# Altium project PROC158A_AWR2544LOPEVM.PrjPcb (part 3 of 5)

## Sheet PROC158A_Ethernet_PHY.SchDoc
size 431 x 279 mm; Date: Not shown in title block; ApprovedBy: Not shown in title block; CheckedBy: Not shown in title block; Author: Not shown in title block; CompanyName: Not shown in title block; Engineer: Not shown in title block; Organization: Not shown in title block; Address1: Not shown in title block; Address2: Not shown in title block; Address3: Not shown in title block; Address4: Not shown in title block; DocumentNumber: 12; Revision: Use project parameter SCH_Rev; SheetNumber: 12; SheetTotal: 24; PageSetup: Record=PageOptions¦CenterHorizontal=True¦CenterVertical=True¦PrintScale=1.00¦XCorrection=1.00¦YCorrection=1.00¦PrintKind=0¦BorderSize=5000000¦LeftOffset=0¦BottomOffset=0¦Orientation=2¦PaperLength=1000¦PaperWidth=1000¦Scale=100¦PaperSource=15¦PrintQuality=600¦MediaType=1¦DitherType=10¦PaperKind=Letter¦PrintScaleMode=1
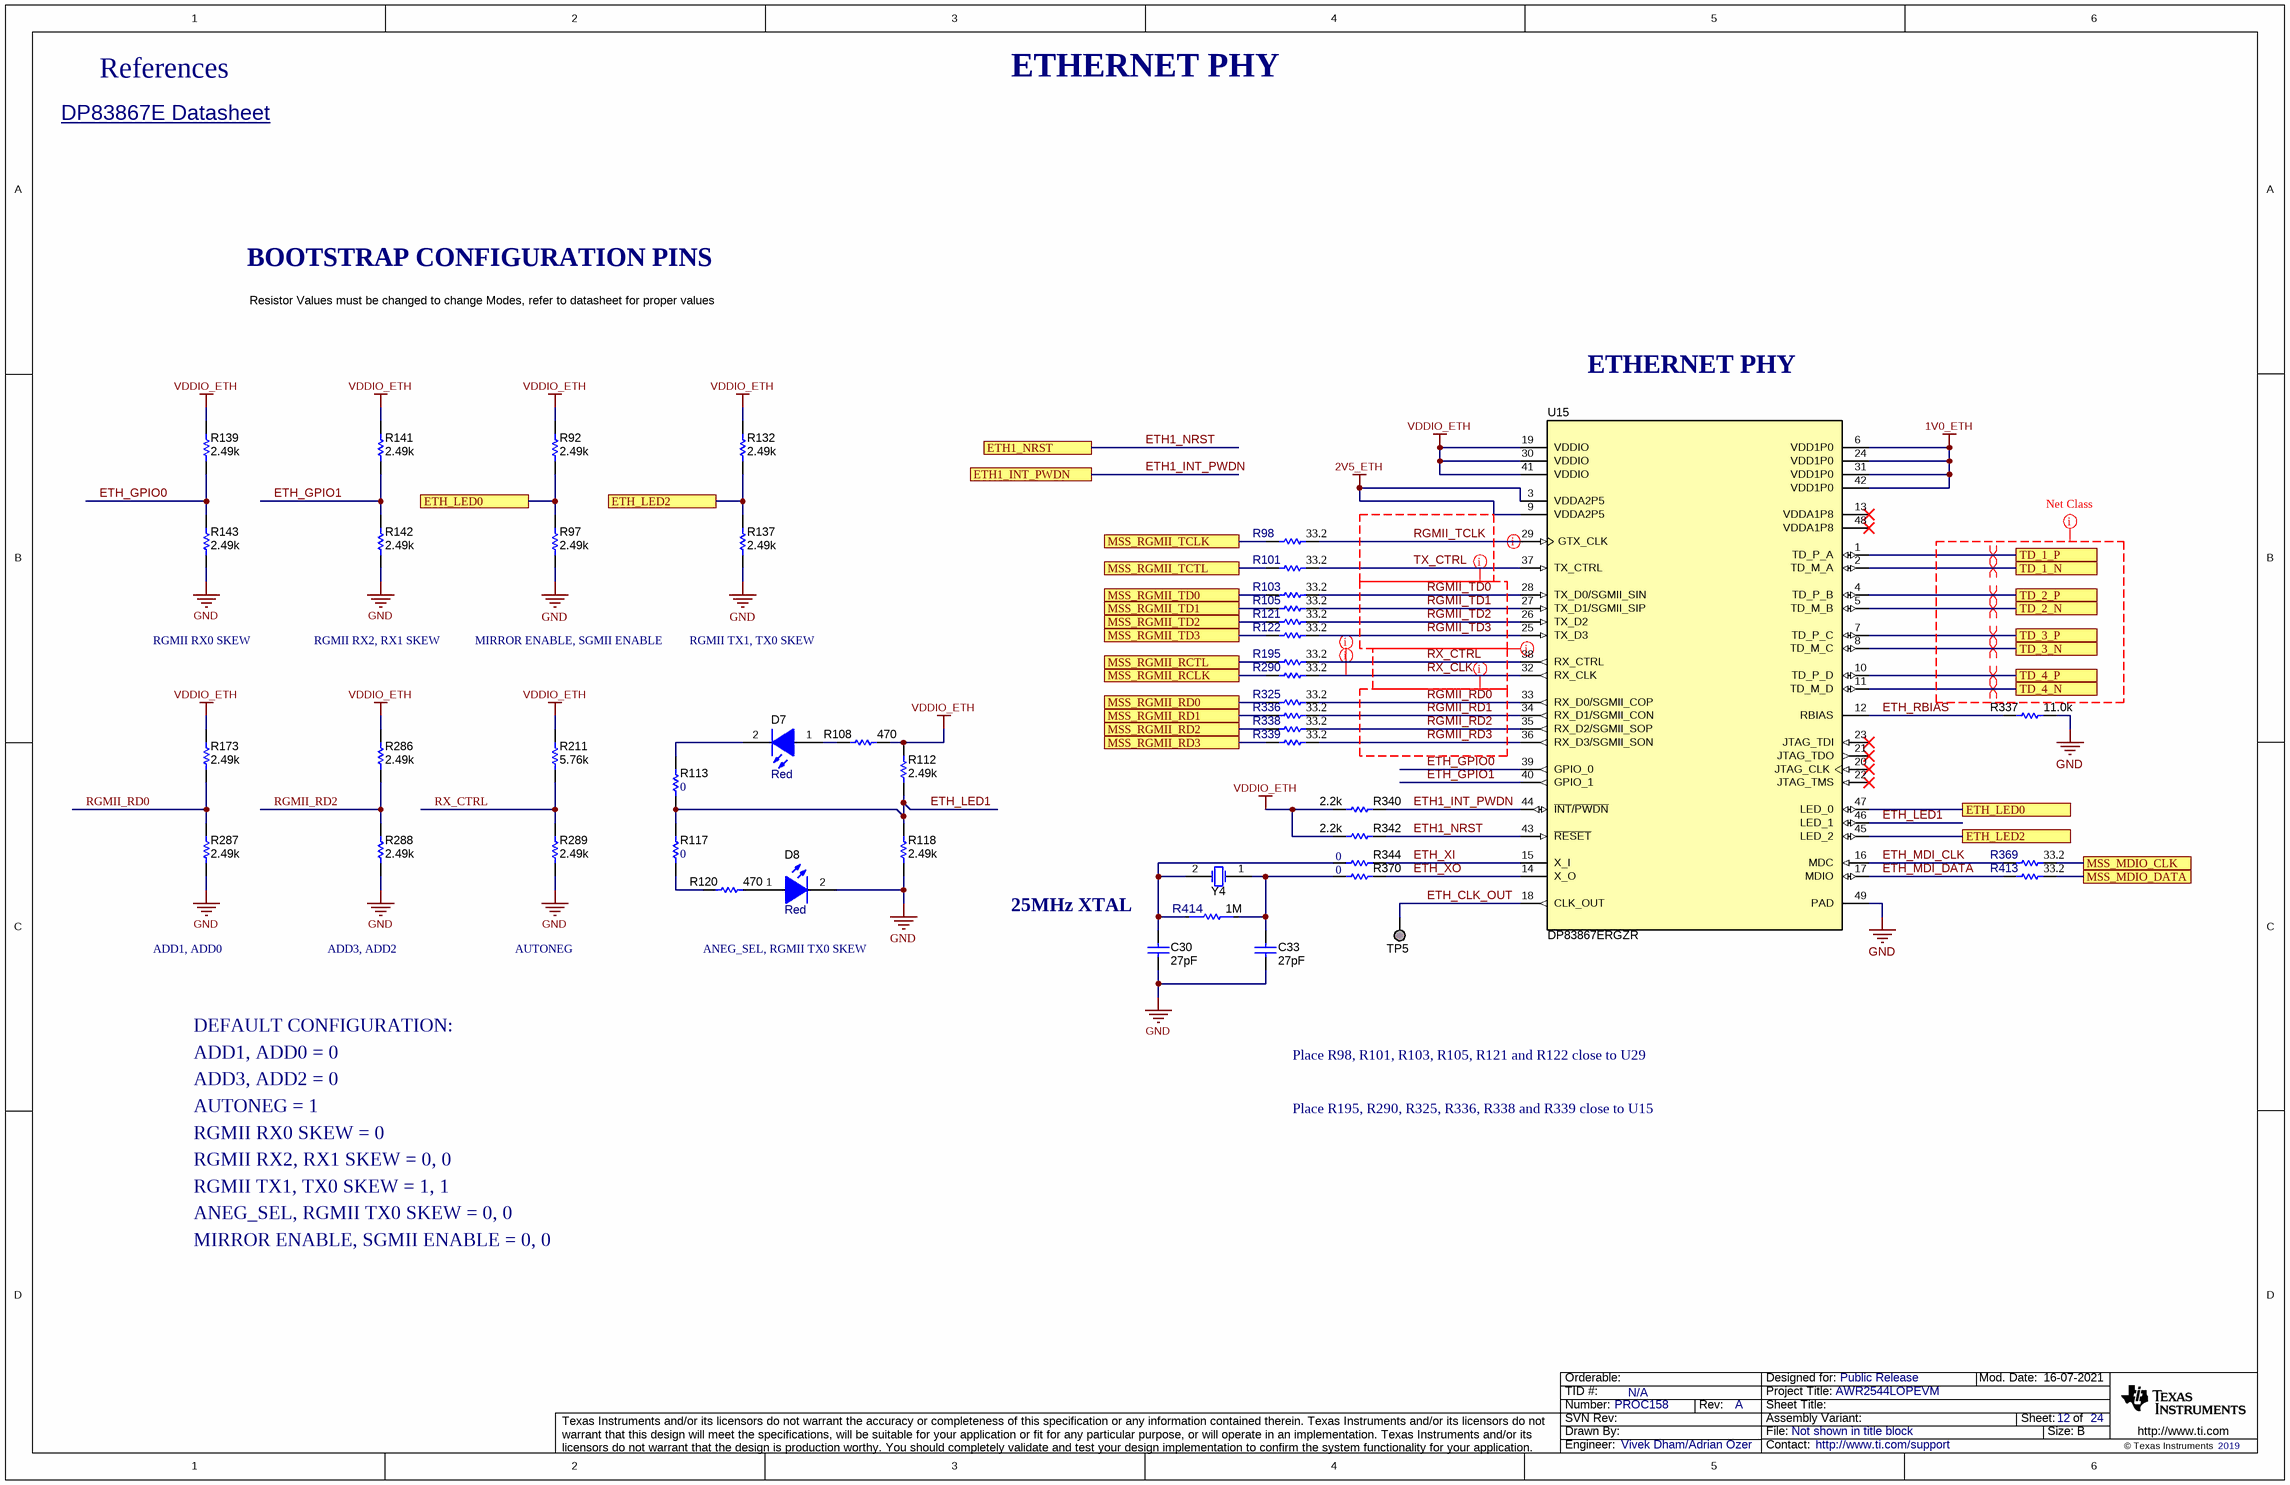
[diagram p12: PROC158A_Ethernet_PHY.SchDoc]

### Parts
C30  ValueDisplayed: 27pF  [0402L]  (hidden comment: GCM1555C1H270JA16D)
C33  ValueDisplayed: 27pF  [0402L]  (hidden comment: GCM1555C1H270JA16D)
D7  value Red  [LS L29K_Red]  (hidden comment: LS L29K-G1J2-1-Z)
D8  value Red  [LS L29K_Red]  (hidden comment: LS L29K-G1J2-1-Z)
R92  ValueDisplayed: 2.49k  [0402L]  (hidden comment: CRCW04022K49FKED)
R97  ValueDisplayed: 2.49k  [0402L]  (hidden comment: CRCW04022K49FKED)
R98  ValueDisplayed: 33.2  [0402L]  (hidden comment: CRCW040233R2FKED)
R101  ValueDisplayed: 33.2  [0402L]  (hidden comment: CRCW040233R2FKED)
R103  ValueDisplayed: 33.2  [0402L]  (hidden comment: CRCW040233R2FKED)
R105  ValueDisplayed: 33.2  [0402L]  (hidden comment: CRCW040233R2FKED)
R108  ValueDisplayed: 470  [0402L]  (hidden comment: ERJ-2RKF4700X)
R112  ValueDisplayed: 2.49k  [0402L]  (hidden comment: CRCW04022K49FKED)
R113  ValueDisplayed: 0  [0402L]  (hidden comment: ERJ-2GE0R00X)
R117  ValueDisplayed: 0  [0402L]  (hidden comment: ERJ-2GE0R00X)
R118  ValueDisplayed: 2.49k  [0402L]  (hidden comment: CRCW04022K49FKED)
R120  ValueDisplayed: 470  [0402L]  (hidden comment: ERJ-2RKF4700X)
R121  ValueDisplayed: 33.2  [0402L]  (hidden comment: CRCW040233R2FKED)
R122  ValueDisplayed: 33.2  [0402L]  (hidden comment: CRCW040233R2FKED)
R132  ValueDisplayed: 2.49k  [0402L]  (hidden comment: CRCW04022K49FKED)
R137  ValueDisplayed: 2.49k  [0402L]  (hidden comment: CRCW04022K49FKED)
R139  ValueDisplayed: 2.49k  [0402L]  (hidden comment: CRCW04022K49FKED)
R141  ValueDisplayed: 2.49k  [0402L]  (hidden comment: CRCW04022K49FKED)
R142  ValueDisplayed: 2.49k  [0402L]  (hidden comment: CRCW04022K49FKED)
R143  ValueDisplayed: 2.49k  [0402L]  (hidden comment: CRCW04022K49FKED)
R173  ValueDisplayed: 2.49k  [0402L]  (hidden comment: CRCW04022K49FKED)
R195  ValueDisplayed: 33.2  [0402L]  (hidden comment: CRCW040233R2FKED)
R211  ValueDisplayed: 5.76k  [0402L]  (hidden comment: CRCW04025K76FKED)
R286  ValueDisplayed: 2.49k  [0402L]  (hidden comment: CRCW04022K49FKED)
R287  ValueDisplayed: 2.49k  [0402L]  (hidden comment: CRCW04022K49FKED)
R288  ValueDisplayed: 2.49k  [0402L]  (hidden comment: CRCW04022K49FKED)
R289  ValueDisplayed: 2.49k  [0402L]  (hidden comment: CRCW04022K49FKED)
R290  ValueDisplayed: 33.2  [0402L]  (hidden comment: CRCW040233R2FKED)
R325  ValueDisplayed: 33.2  [0402L]  (hidden comment: CRCW040233R2FKED)
R336  ValueDisplayed: 33.2  [0402L]  (hidden comment: CRCW040233R2FKED)
R337  ValueDisplayed: 11.0k  [0402L]  (hidden comment: CRCW040211K0FKED)
R338  ValueDisplayed: 33.2  [0402L]  (hidden comment: CRCW040233R2FKED)
R339  ValueDisplayed: 33.2  [0402L]  (hidden comment: CRCW040233R2FKED)
R340  ValueDisplayed: 2.2k  [0402L]  (hidden comment: CRCW04022K20JNED)
R342  ValueDisplayed: 2.2k  [0402L]  (hidden comment: CRCW04022K20JNED)
R344  ValueDisplayed: 0  [0201L]  (hidden comment: CRCW02010000Z0ED)
R369  ValueDisplayed: 33.2  [0402L]  (hidden comment: CRCW040233R2FKED)
R370  ValueDisplayed: 0  [0201L]  (hidden comment: CRCW02010000Z0ED)
R413  ValueDisplayed: 33.2  [0402L]  (hidden comment: CRCW040233R2FKED)
R414  Res_ohm: 1M  [FP-CRCW06031M00FKEAC_0603-MFG]  (hidden comment: CRCW06031M00FKEAC)
TP5  TESTPOINT  [TP_25MIL-SMT]  (value not drawn)  (no BOM)
U15  DP83867ERGZR  [RGZ0048B]
Y4  ABM3-25.000MHZ-D2Y-T  [XTAL_ABM3]  (value not drawn)

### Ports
ETH1_INT_PWDN, ETH1_NRST, ETH_LED0, ETH_LED2, MSS_MDIO_CLK, MSS_MDIO_DATA, MSS_RGMII_RCLK, MSS_RGMII_RCTL, MSS_RGMII_RD0, MSS_RGMII_RD1, MSS_RGMII_RD2, MSS_RGMII_RD3, MSS_RGMII_TCLK, MSS_RGMII_TCTL, MSS_RGMII_TD0, MSS_RGMII_TD1, MSS_RGMII_TD2, MSS_RGMII_TD3, TD_1_N, TD_1_P, TD_2_N, TD_2_P, TD_3_N, TD_3_P, TD_4_N, TD_4_P

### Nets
1V0_ETH: U15.6(VDD1P0) U15.24(VDD1P0) U15.31(VDD1P0) U15.42(VDD1P0)
2V5_ETH: U15.3(VDDA2P5) U15.9(VDDA2P5)
GND: C30.2 C33.2 D8.2(K) R97.1 R118.1 R137.1 R142.1 R143.1 R287.1 R288.1 R289.1 R337.2 U15.49(PAD)
VDDIO_ETH: R92.2 R108.2 R112.2 R132.2 R139.2 R141.2 R173.2 R211.2 R286.2 R340.2 R342.2 U15.19(VDDIO) U15.30(VDDIO) U15.41(VDDIO)
ETH1_INT_PWDN: R340.1 U15.44(~{INT}/~{PWDN}) ; port ETH1_INT_PWDN
ETH1_NRST: R342.1 U15.43(~{RESET}) ; port ETH1_NRST
ETH_CLK_OUT: TP5.1 U15.18(CLK_OUT)
ETH_GPIO0: R139.1 R143.2 U15.39(GPIO_0)
ETH_GPIO1: R141.1 R142.2 U15.40(GPIO_1)
ETH_LED0: R92.1 R97.2 U15.47(LED_0) ; port ETH_LED0
ETH_LED1: R112.1 R113.1 R117.2 R118.2 U15.46(LED_1)
ETH_LED2: R132.1 R137.2 U15.45(LED_2) ; port ETH_LED2
ETH_MDI_CLK: R369.1 U15.16(MDC)
ETH_MDI_DATA: R413.1 U15.17(MDIO)
ETH_RBIAS: R337.1 U15.12(RBIAS)
ETH_XI: R344.2 U15.15(X_I)
ETH_XO: R370.2 U15.14(X_O)
MSS_MDIO_CLK: R369.2 ; port MSS_MDIO_CLK
MSS_MDIO_DATA: R413.2 ; port MSS_MDIO_DATA
MSS_RGMII_RCLK: R290.1 ; port MSS_RGMII_RCLK
MSS_RGMII_RCTL: R195.1 ; port MSS_RGMII_RCTL
MSS_RGMII_RD0: R325.1 ; port MSS_RGMII_RD0
MSS_RGMII_RD1: R336.1 ; port MSS_RGMII_RD1
MSS_RGMII_RD2: R338.1 ; port MSS_RGMII_RD2
MSS_RGMII_RD3: R339.1 ; port MSS_RGMII_RD3
MSS_RGMII_TCLK: R98.1 ; port MSS_RGMII_TCLK
MSS_RGMII_TCTL: R101.1 ; port MSS_RGMII_TCTL
MSS_RGMII_TD0: R103.1 ; port MSS_RGMII_TD0
MSS_RGMII_TD1: R105.1 ; port MSS_RGMII_TD1
MSS_RGMII_TD2: R121.1 ; port MSS_RGMII_TD2
MSS_RGMII_TD3: R122.1 ; port MSS_RGMII_TD3
RGMII_RD0: R173.1 R287.2 R325.2 U15.33(RX_D0/SGMII_COP)
RGMII_RD1: R336.2 U15.34(RX_D1/SGMII_CON)
RGMII_RD2: R286.1 R288.2 R338.2 U15.35(RX_D2/SGMII_SOP)
RGMII_RD3: R339.2 U15.36(RX_D3/SGMII_SON)
RGMII_TCLK: R98.2 U15.29(GTX_CLK)
RGMII_TD0: R103.2 U15.28(TX_D0/SGMII_SIN)
RGMII_TD1: R105.2 U15.27(TX_D1/SGMII_SIP)
RGMII_TD2: R121.2 U15.26(TX_D2)
RGMII_TD3: R122.2 U15.25(TX_D3)
RX_CLK: R290.2 U15.32(RX_CLK)
RX_CTRL: R195.2 R211.1 R289.2 U15.38(RX_CTRL)
TD_1_N: U15.2(TD_M_A) ; port TD_1_N
TD_1_P: U15.1(TD_P_A) ; port TD_1_P
TD_2_N: U15.5(TD_M_B) ; port TD_2_N
TD_2_P: U15.4(TD_P_B) ; port TD_2_P
TD_3_N: U15.8(TD_M_C) ; port TD_3_N
TD_3_P: U15.7(TD_P_C) ; port TD_3_P
TD_4_N: U15.11(TD_M_D) ; port TD_4_N
TD_4_P: U15.10(TD_P_D) ; port TD_4_P
TX_CTRL: R101.2 U15.37(TX_CTRL)
NetC30_1: C30.1 R344.1 R414.1 Y4.2(OSC2)
NetC33_1: C33.1 R370.1 R414.2 Y4.1(OSC1)
NetD7_1: D7.1(A) R108.1
NetD7_2: D7.2(K) R113.2
NetD8_1: D8.1(A) R120.2
NetR117_1: R117.1 R120.1

Not connected (* = marked no-connect by the designer): U15 13(VDDA1P8)* 20(JTAG_CLK)* 21(JTAG_TDO)* 22(JTAG_TMS)* 23(JTAG_TDI)* 48(VDDA1P8)*

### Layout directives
net class RGMII; net class RGMII_TX_RX: RGMII_RD0, RGMII_RD1, RGMII_RD2, RGMII_RD3, RGMII_TD0, RGMII_TD1, RGMII_TD2, RGMII_TD3
net class RGMII: (no net found under the mark), RX_CLK, RX_CTRL
differential pair: TD_1_N, TD_1_P, TD_2_N, TD_2_P, TD_3_N, TD_3_P, TD_4_N, TD_4_P
net class RGMII_TX_RX: RGMII_TCLK, RGMII_TD0, RGMII_TD1, RGMII_TD2, RGMII_TD3

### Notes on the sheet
- References
- ETHERNET PHY
- DP83867E Datasheet <http://www.ti.com/lit/ds/symlink/dp83867e.pdf>
- BOOTSTRAP CONFIGURATION PINS
- Resistor Values must be changed to change Modes, refer to datasheet for proper values
- RGMII RX0 SKEW
- RGMII RX2, RX1 SKEW
- MIRROR ENABLE, SGMII ENABLE
- RGMII TX1, TX0 SKEW
- ADD1, ADD0
- ADD3, ADD2
- AUTONEG
- ANEG_SEL, RGMII TX0 SKEW
- 25MHz XTAL
- DEFAULT CONFIGURATION:
- ADD1, ADD0 = 0
- ADD3, ADD2 = 0
- Place R98, R101, R103, R105, R121 and R122 close to U29
- AUTONEG = 1
- RGMII RX2, RX1 SKEW = 0, 0
- RGMII RX0 SKEW = 0
- Place R195, R290, R325, R336, R338 and R339 close to U15
- RGMII TX1, TX0 SKEW = 1, 1
- ANEG_SEL, RGMII TX0 SKEW = 0, 0
- MIRROR ENABLE, SGMII ENABLE = 0, 0

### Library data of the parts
C30 C33 = CMP-0860920-1: CAP, CERM, 27 pF, 50 V,+/- 5%, C0G/NP0, AEC-Q200 Grade 1, 0402; Manufacturer: MuRata; AEC Grade: 1; SizeZ_mm: 0.6; U/M: EA; Value: 27pF; SizeY_mm: 0.5; TaMax_C: 125°C; Polarized: N; AEC Qualified: Y; Cap_Case: 0402; AEC Category: Q200; Value2: 50V; SizeAreaWB_mm2: 3; TaMin_C: -55°C
D7 D8 = CMP-0002902-2: LED, Red, SMD; Manufacturer: OSRAM; Tjmax_C: 110°C; Vf_V: 1.8V; Vr_V: 12V; Io_A: 20mA; Angle: 160; Value1: W
R92 R97 R112 R118 R132 R137 R139 R141-R143 R173 R286-R289 = CMP-0026237-2: RES, 2.49 k, 1%, 0.063 W, AEC-Q200 Grade 0, 0402; Manufacturer: Vishay-Dale; Power_W: 63mW; TempCo: 100 ppm/C; Value_Code: 2k49; Value: 2.49k; EIA_Code: E96; SizeX_mm: 1; SizeY_mm: 0.5; SizeZ_mm: 0.6; Value2: 0.063W; AEC Qualified: Y; VDC_V: 50V; AEC Category: Q200; AEC Grade: 0
R98 R101 R103 R105 R121 R122 R195 R290 R325 R336 R338 R339 R369 R413 = CMP-0026299-2: RES, 33.2, 1%, 0.063 W, AEC-Q200 Grade 0, 0402; Manufacturer: Vishay-Dale; Power_W: 63mW; TempCo: 100 ppm/C; Value_Code: 33R2; Value: 33.2; EIA_Code: E96; SizeX_mm: 1; SizeY_mm: 0.5; SizeZ_mm: 0.6; Value2: 0.063W; AEC Qualified: Y; VDC_V: 50V; AEC Category: Q200; AEC Grade: 0
R108 R120 = CMP-0026699-1: RES, 470, 1%, 0.1 W, AEC-Q200 Grade 0, 0402; Manufacturer: Panasonic; Power_W: 100mW; TempCo: 100 ppm/C; Value_Code: 470R; U/M: EA; Value: 470; SizeX_mm: 1; SizeY_mm: 0.5; SizeZ_mm: 0.6; Value2: 0.1W; AEC Qualified: Y; VDC_V: 50V; AEC Grade: 0; AEC Category: Q200
R113 R117 = CMP-0026992-3: RES, 0, 5%, 0.1 W, AEC-Q200 Grade 0, 0402; Manufacturer: Panasonic; Power_W: 100mW; TempCo: 600 ppm/C; Value_Code: 0000; Value: 0; EIA_Code: E24; SizeX_mm: 1; SizeY_mm: 0.5; SizeZ_mm: 0.6; Value2: 0.1W; CompType: Resistor; AEC Qualified: Y; VDC_V: 50V; AEC Category: Q200; SizeAreaWB_mm2: 3; INSTALLATION: DNP
R211 = CMP-0026468-2: RES, 5.76 k, 1%, 0.063 W, AEC-Q200 Grade 0, 0402; Manufacturer: Vishay-Dale; Power_W: 63mW; TempCo: 100 ppm/C; Value_Code: 5k76; Value: 5.76k; EIA_Code: E96; SizeX_mm: 1; SizeY_mm: 0.5; SizeZ_mm: 0.6; Value2: 0.063W; AEC Qualified: Y; VDC_V: 50V; AEC Category: Q200; AEC Grade: 0
R337 = CMP-0025975-3: RES, 11.0 k, 1%, 0.063 W, AEC-Q200 Grade 0, 0402; Manufacturer: Vishay-Dale; Power_W: 63mW; TempCo: 100 ppm/C; Value_Code: 11k0; Value: 11.0k; EIA_Code: E96; Res_ohm: 11k; SizeX_mm: 1; SizeY_mm: 0.5; SizeZ_mm: 0.6; Value2: 0.063W; AEC Qualified: Y; VDC_V: 50V; AEC Category: Q200; AEC Grade: 0
R340 R342 = CMP-0026890-5: RES, 2.2 k, 5%, 0.063 W, AEC-Q200 Grade 0, 0402; Manufacturer: Vishay-Dale; Power_W: 63mW; TempCo: 200 ppm/C; Value_Code: 2k20; Value: 2.2k; EIA_Code: E24; SizeX_mm: 1; SizeY_mm: 0.5; SizeZ_mm: 0.6; Value2: 0.063W; AEC Qualified: Y; VDC_V: 50V; AEC Category: Q200; AEC Grade: 0
R344 R370 = CMP-0027008-4: RES, 0, 5%, 0.05 W, 0201; Manufacturer: Vishay-Dale; Power_W: 50mW; TempCo: ppm/C; Value_Code: 0000; Value: 0; EIA_Code: E24; SizeX_mm: 0.6; SizeY_mm: 0.3; SizeZ_mm: 0.26; Value2: 0.05W; SizeArea_mm2: 0.18; AEC Qualified: N; AEC Category: Q200
R414 = CMP-0089574-2: Res Thick Film 0603 1M Ohm 1% 1/10W ±100ppm/°C Molded SMD Paper T/R; Manufacturer: Vishay; AEC Qualified: No; Power_W: 100mW; AEC Grade: NA; SizeZ_mm: 0.55mm; VDC_V: 75V
TP5 = CMP-0078143-3: TEST POINT.  No entry in BOM.
U15 = CMP-0076013-2: Extended Temperature Gigabit Ethernet PHY with SGMII, RGZ0048B (VQFN-48); Manufacturer: Texas Instruments; Alternate PartNumber: DP83867ERGZT; SizeX_mm: 7; CompType: IC; SizeZ_mm: 1; SizeArea_mm2: 49; SizeAreaWB_mm2: 81; U/M: EA
Y4 = CMP-0004620-3: Crystal, 25 MHz, 18 pF, SMD; Manufacturer: Abracon Corporation; TaMin_C: -40°C; Frequency Stability: +/-30ppm; Frequency_Fixed: 25MHz; TaMax_C: 85°C

## Sheet PROC158A_Ethernet_Magnetics.SchDoc
size 431 x 279 mm; Date: Not shown in title block; ApprovedBy: Not shown in title block; CheckedBy: Not shown in title block; Author: Not shown in title block; CompanyName: Not shown in title block; Engineer: Not shown in title block; Organization: Not shown in title block; Address1: Not shown in title block; Address2: Not shown in title block; Address3: Not shown in title block; Address4: Not shown in title block; DocumentNumber: 13; Revision: Use project parameter SCH_Rev; SheetNumber: 13; SheetTotal: 24; PageSetup: Record=PageOptions¦CenterHorizontal=True¦CenterVertical=True¦PrintScale=1.00¦XCorrection=1.00¦YCorrection=1.00¦PrintKind=0¦BorderSize=5000000¦LeftOffset=0¦BottomOffset=0¦Orientation=2¦PaperLength=1000¦PaperWidth=1000¦Scale=100¦PaperSource=15¦PrintQuality=600¦MediaType=1¦DitherType=10¦PaperKind=Letter¦PrintScaleMode=1
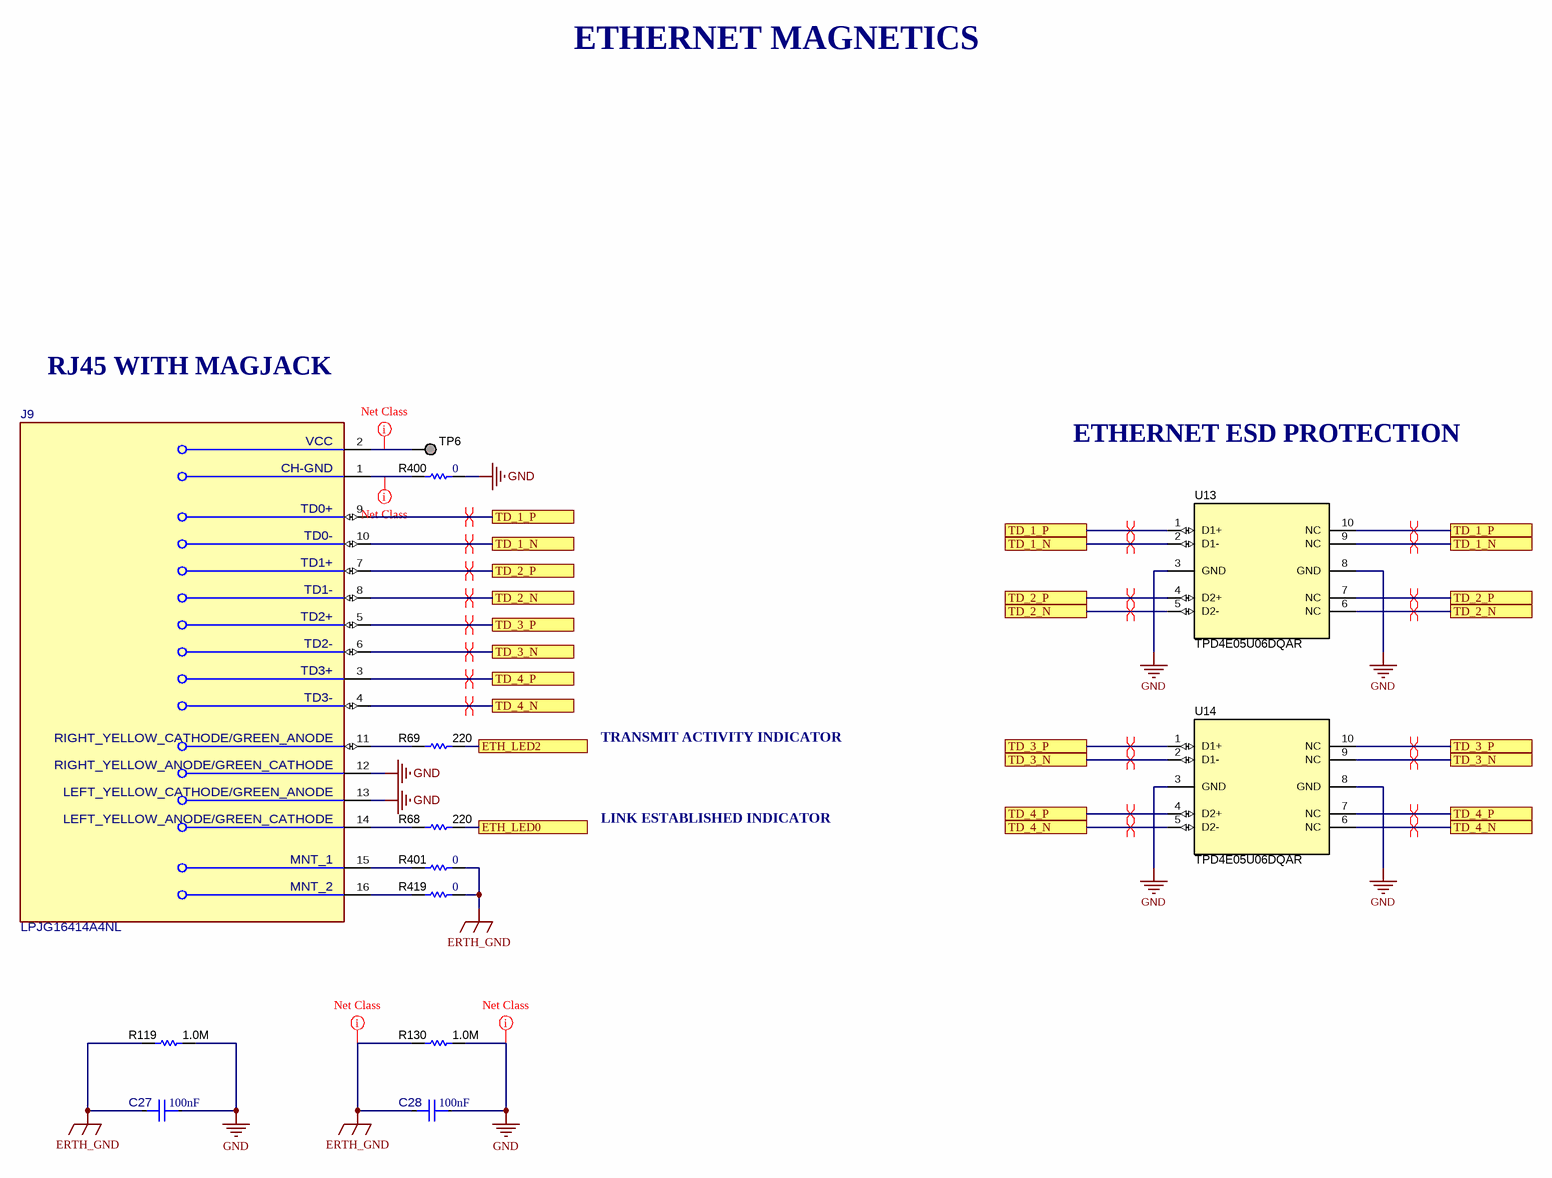
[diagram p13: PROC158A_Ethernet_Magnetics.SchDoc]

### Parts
C27  Cap_F: 100nF  [FP-C0603C104K4RACAUTO_0603-MFG]  (hidden comment: C0603C104K4RACAUTO)
C28  Cap_F: 100nF  [FP-C0603C104K4RACAUTO_0603-MFG]  (hidden comment: C0603C104K4RACAUTO)
J9  LPJG16414A4NL  [FP-LPJG16414A4NL_CONN_RJ45-MFG]
R68  ValueDisplayed: 220  [0402L]  (hidden comment: CRCW0402220RJNED)
R69  ValueDisplayed: 220  [0402L]  (hidden comment: CRCW0402220RJNED)
R119  ValueDisplayed: 1.0M  [1206L]  (hidden comment: CRCW12061M00JNEA)
R130  ValueDisplayed: 1.0M  [1206L]  (hidden comment: CRCW12061M00JNEA)
R400  ValueDisplayed: 0  [0402L]  (hidden comment: ERJ-2GE0R00X)
R401  ValueDisplayed: 0  [0402L]  (hidden comment: ERJ-2GE0R00X)
R419  ValueDisplayed: 0  [0402L]  (hidden comment: ERJ-2GE0R00X)
TP6  TESTPOINT  [TP_25MIL-SMT]  (value not drawn)  (no BOM)
U13  TPD4E05U06DQAR  [DQA0010A]
U14  TPD4E05U06DQAR  [DQA0010A]

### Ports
ETH_LED0, ETH_LED2, TD_1_N, TD_1_P, TD_2_N, TD_2_P, TD_3_N, TD_3_P, TD_4_N, TD_4_P

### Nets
ERTH_GND: C27.2 C28.2 R119.1 R130.1 R401.2 R419.2
GND: C27.1 C28.1 J9.12(RIGHT_YELLOW_ANODE/GREEN_CATHODE) J9.13(LEFT_YELLOW_CATHODE/GREEN_ANODE) R119.2 R130.2 R400.2 U13.3(GND) U13.8(GND) U14.3(GND) U14.8(GND)
ETH_LED0: R68.1 ; port ETH_LED0
ETH_LED2: R69.2 ; port ETH_LED2
TD_1_N: J9.10(TD0-) U13.2(D1-) U13.9(NC) ; port TD_1_N
TD_1_P: J9.9(TD0+) U13.1(D1+) U13.10(NC) ; port TD_1_P
TD_2_N: J9.8(TD1-) U13.5(D2-) U13.6(NC) ; port TD_2_N
TD_2_P: J9.7(TD1+) U13.4(D2+) U13.7(NC) ; port TD_2_P
TD_3_N: J9.6(TD2-) U14.2(D1-) U14.9(NC) ; port TD_3_N
TD_3_P: J9.5(TD2+) U14.1(D1+) U14.10(NC) ; port TD_3_P
TD_4_N: J9.4(TD3-) U14.5(D2-) U14.6(NC) ; port TD_4_N
TD_4_P: J9.3(TD3+) U14.4(D2+) U14.7(NC) ; port TD_4_P
NetJ9_1: J9.1(CH-GND) R400.1
NetJ9_2: J9.2(VCC) TP6.1
NetJ9_11: J9.11(RIGHT_YELLOW_CATHODE/GREEN_ANODE) R69.1
NetJ9_14: J9.14(LEFT_YELLOW_ANODE/GREEN_CATHODE) R68.2
NetJ9_15: J9.15(MNT_1) R401.1
NetJ9_16: J9.16(MNT_2) R419.1

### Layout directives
differential pair: TD_1_N, TD_1_P, TD_2_N, TD_2_P, TD_3_N, TD_3_P, TD_4_N, TD_4_P
net class PWR: ERTH_GND, GND, NetJ9_1, NetJ9_2

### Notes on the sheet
- ETHERNET MAGNETICS
- RJ45 WITH MAGJACK
- ETHERNET ESD PROTECTION
- TRANSMIT ACTIVITY INDICATOR
- LINK ESTABLISHED INDICATOR

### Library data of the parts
C27 C28 = CMP-0089508-1: C0603 0.10 μF X7R 30ppm/°C 10.00% 16 V; Manufacturer: KEMET; AEC Qualified: Yes; Tolerance_%: 0.1%; VDC_V: 16V; ValueDisplayed: 0.10 μF; AEC Grade: Grade 1; SizeZ_mm: 0.87mm
J9 = CMP-0088394-1: RJ45 Connector with 1000 Base-TX Inetgrated Magnetic; Manufacturer: LINK-PP; DUT-Pitch_mm: 1.27mm; Conn Orientation: Horizontal; ContactFinish: Gold; Conn Gender: Female; Is Female: yes; AEC Qualified: No; Shrouded: true
R68 R69 = CMP-0026878-3: RES, 220, 5%, 0.063 W, AEC-Q200 Grade 0, 0402; Manufacturer: Vishay-Dale; Power_W: 63mW; TempCo: 200 ppm/C; Value_Code: 220R; Value: 220; EIA_Code: E24; SizeX_mm: 1; SizeY_mm: 0.5; SizeZ_mm: 0.6; Value2: 0.063W; AEC Qualified: Y; VDC_V: 50V; AEC Category: Q200; AEC Grade: 0
R119 R130 = CMP-0018610-3: RES, 1.0 M, 5%, 0.25 W, AEC-Q200 Grade 0, 1206; Manufacturer: Vishay-Dale; Power_W: 250mW; TempCo: 200 ppm/C; Value_Code: 1M00; Value: 1.0Meg; EIA_Code: E24; Res_ohm: 1M; SizeX_mm: 3.2; SizeY_mm: 1.6; SizeZ_mm: 1.35; Value2: 0.25W; SizeArea_mm2: 5.12; AEC Qualified: Y; VDC_V: 200V; AEC Category: Q200; AEC Grade: 0
R400 R401 R419 = CMP-0026992-3: as R113 on sheet PROC158A_Ethernet_PHY
TP6 = CMP-0078143-3: TEST POINT.  No entry in BOM.
U13 U14 = CMP-0073613-3: 4-Channel Ultra-Low-Capacitance IEC ESD Protection Diode, DQA0010A (USON-10); Alternate Manufacturer: Texas Instruments; Green_Lifecycle: Active; SizeAreaWB_mm2: 7.0; Green_REACh: Passed; SizeZ_mm: 0.55; SizeX_mm: 1.0; SizeY_mm: 2.5; CompType: IC; AEC Category: Q200; AEC Qualified: N

## Sheet PROC158A_Auto_Ethernet_PHY.SchDoc
size 431 x 279 mm; Date: Not shown in title block; ApprovedBy: Not shown in title block; CheckedBy: Not shown in title block; Author: Not shown in title block; CompanyName: Not shown in title block; Engineer: Not shown in title block; Organization: Not shown in title block; Address1: Not shown in title block; Address2: Not shown in title block; Address3: Not shown in title block; Address4: Not shown in title block; DocumentNumber: 14; Revision: Use project parameter SCH_Rev; SheetNumber: 14; SheetTotal: 24; PageSetup: Record=PageOptions¦CenterHorizontal=True¦CenterVertical=True¦PrintScale=1.00¦XCorrection=1.00¦YCorrection=1.00¦PrintKind=0¦BorderSize=5000000¦LeftOffset=0¦BottomOffset=0¦Orientation=2¦PaperLength=1000¦PaperWidth=1000¦Scale=100¦PaperSource=15¦PrintQuality=600¦MediaType=1¦DitherType=10¦PaperKind=Letter¦PrintScaleMode=1
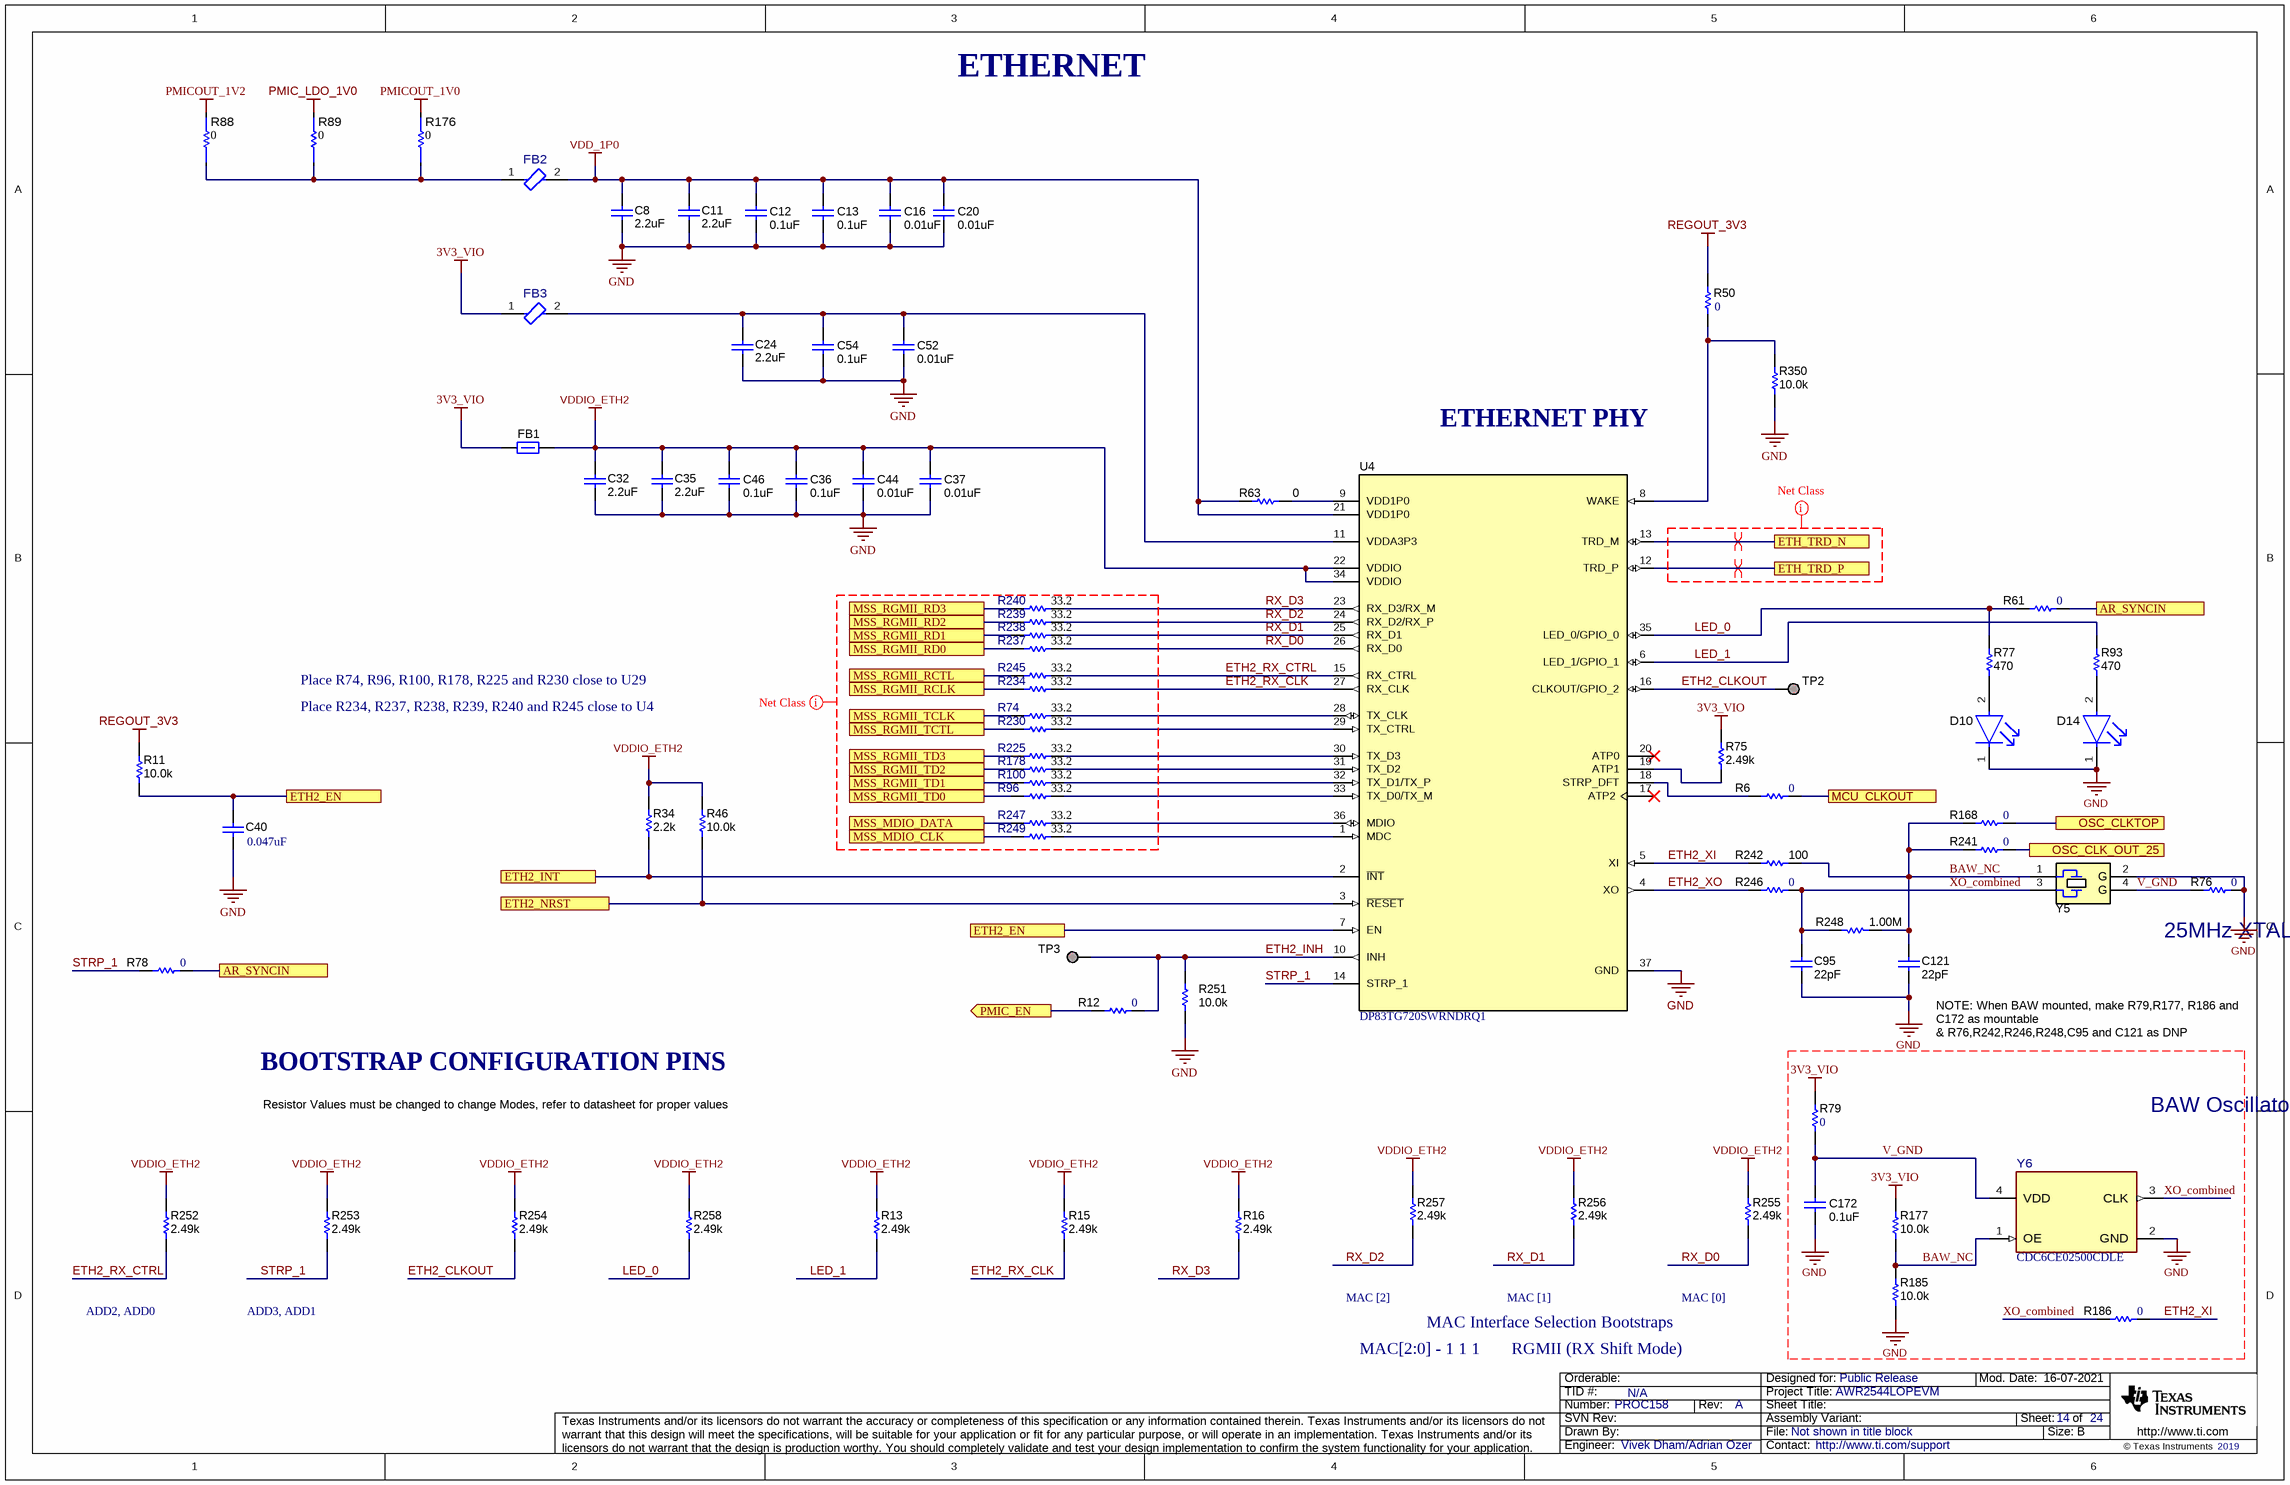
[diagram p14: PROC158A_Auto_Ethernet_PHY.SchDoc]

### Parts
C8  ValueDisplayed: 2.2uF  [0603L]  (hidden comment: GCM188R70J225KE22D)
C11  ValueDisplayed: 2.2uF  [0603L]  (hidden comment: GCM188R70J225KE22D)
C12  ValueDisplayed: 0.1uF  [0402L]  (hidden comment: GCM155R71C104KA55D)
C13  ValueDisplayed: 0.1uF  [0402L]  (hidden comment: GCM155R71C104KA55D)
C16  ValueDisplayed: 0.01uF  [0402L]  (hidden comment: CGA2B3X7R1H103K050BB)
C20  ValueDisplayed: 0.01uF  [0402L]  (hidden comment: CGA2B3X7R1H103K050BB)
C24  ValueDisplayed: 2.2uF  [0603L]  (hidden comment: GCM188R70J225KE22D)
C32  ValueDisplayed: 2.2uF  [0603L]  (hidden comment: GCM188R70J225KE22D)
C35  ValueDisplayed: 2.2uF  [0603L]  (hidden comment: GCM188R70J225KE22D)
C36  ValueDisplayed: 0.1uF  [0402L]  (hidden comment: GCM155R71C104KA55D)
C37  ValueDisplayed: 0.01uF  [0402L]  (hidden comment: CGA2B3X7R1H103K050BB)
C40  ValueDisplayed: 0.047uF  [0402]  (hidden comment: GRM155R71E473KA88D)
C44  ValueDisplayed: 0.01uF  [0402L]  (hidden comment: CGA2B3X7R1H103K050BB)
C46  ValueDisplayed: 0.1uF  [0402L]  (hidden comment: GCM155R71C104KA55D)
C52  ValueDisplayed: 0.01uF  [0402L]  (hidden comment: CGA2B3X7R1H103K050BB)
C54  ValueDisplayed: 0.1uF  [0402L]  (hidden comment: GCM155R71C104KA55D)
C95  ValueDisplayed: 22pF  [0603]  (hidden comment: CGA3E2C0G1H220J080AA)
C121  ValueDisplayed: 22pF  [0603]  (hidden comment: CGA3E2C0G1H220J080AA)
C172  ValueDisplayed: 0.1uF  [0402L]  (hidden comment: GCM155R71C104KA55D)
D10  SML-P12YTT86R  [FP-SML-P12YTT86R_0402-MFG]  (value not drawn)
D14  SML-P12DTT86R  [FP-SML-P12DTT86R_0402-MFG]  (value not drawn)
FB1  BLM18HE102SN1D  [0603]  (value not drawn)
FB2  BLM18KG601SH1  [FP-BLM18KG601SH1_0603 (1608 Metric)-MFG]  (value not drawn)
FB3  BLM18KG601SH1  [FP-BLM18KG601SH1_0603 (1608 Metric)-MFG]  (value not drawn)
R6  ValueDisplayed: 0  [0402L]  (hidden comment: ERJ-2GE0R00X)
R11  ValueDisplayed: 10.0k  [0402L]  (hidden comment: CRCW040210K0FKED)
R12  ValueDisplayed: 0  [0201L]  (hidden comment: CRCW02010000Z0ED)
R13  ValueDisplayed: 2.49k  [0402L]  (hidden comment: CRCW04022K49FKED)
R15  ValueDisplayed: 2.49k  [0402L]  (hidden comment: CRCW04022K49FKED)
R16  ValueDisplayed: 2.49k  [0402L]  (hidden comment: CRCW04022K49FKED)
R34  ValueDisplayed: 2.2k  [0402L]  (hidden comment: CRCW04022K20JNED)
R46  ValueDisplayed: 10.0k  [0402L]  (hidden comment: CRCW040210K0FKED)
R50  ValueDisplayed: 0  [0402L]  (hidden comment: ERJ-2GE0R00X)
R61  ValueDisplayed: 0  [0201L]  (hidden comment: CRCW02010000Z0ED)
R63  ValueDisplayed: 0  [0402]  (hidden comment: CRCW04020000Z0EDHP)
R74  ValueDisplayed: 33.2  [0402L]  (hidden comment: CRCW040233R2FKED)
R75  ValueDisplayed: 2.49k  [0402L]  (hidden comment: CRCW04022K49FKED)
R76  ValueDisplayed: 0  [0402L]  (hidden comment: ERJ-2GE0R00X)
R77  ValueDisplayed: 470  [0402L]  (hidden comment: ERJ-2RKF4700X)
R78  ValueDisplayed: 0  [0201L]  (hidden comment: CRCW02010000Z0ED)
R79  ValueDisplayed: 0  [0402L]  (hidden comment: ERJ-2GE0R00X)
R88  Res_ohm: 0  [FP-HCJ0603ZT0R00_0603-MFG]  (hidden comment: HCJ0603ZT0R00)
R89  Res_ohm: 0  [FP-HCJ0603ZT0R00_0603-MFG]  (hidden comment: HCJ0603ZT0R00)
R93  ValueDisplayed: 470  [0402L]  (hidden comment: ERJ-2RKF4700X)
R96  ValueDisplayed: 33.2  [0402L]  (hidden comment: CRCW040233R2FKED)
R100  ValueDisplayed: 33.2  [0402L]  (hidden comment: CRCW040233R2FKED)
R168  ValueDisplayed: 0  [0402L]  (hidden comment: ERJ-2GE0R00X)
R176  Res_ohm: 0  [FP-HCJ0603ZT0R00_0603-MFG]  (hidden comment: HCJ0603ZT0R00)
R177  ValueDisplayed: 10.0k  [0402L]  (hidden comment: CRCW040210K0FKED)
R178  ValueDisplayed: 33.2  [0402L]  (hidden comment: CRCW040233R2FKED)
R185  ValueDisplayed: 10.0k  [0402L]  (hidden comment: CRCW040210K0FKED)
R186  ValueDisplayed: 0  [0402L]  (hidden comment: ERJ-2GE0R00X)
R225  ValueDisplayed: 33.2  [0402L]  (hidden comment: CRCW040233R2FKED)
R230  ValueDisplayed: 33.2  [0402L]  (hidden comment: CRCW040233R2FKED)
R234  ValueDisplayed: 33.2  [0402L]  (hidden comment: CRCW040233R2FKED)
R237  ValueDisplayed: 33.2  [0402L]  (hidden comment: CRCW040233R2FKED)
R238  ValueDisplayed: 33.2  [0402L]  (hidden comment: CRCW040233R2FKED)
R239  ValueDisplayed: 33.2  [0402L]  (hidden comment: CRCW040233R2FKED)
R240  ValueDisplayed: 33.2  [0402L]  (hidden comment: CRCW040233R2FKED)
R241  ValueDisplayed: 0  [0402L]  (hidden comment: ERJ-2GE0R00X)
R242  ValueDisplayed: 100  [0402L]  (hidden comment: ERJ-2GEJ101X)
R245  ValueDisplayed: 33.2  [0402L]  (hidden comment: CRCW040233R2FKED)
R246  ValueDisplayed: 0  [0402L]  (hidden comment: ERJ-2GE0R00X)
R247  ValueDisplayed: 33.2  [0402L]  (hidden comment: CRCW040233R2FKED)
R248  ValueDisplayed: 1.00M  [0603L]  (hidden comment: CRCW06031M00FKEA)
R249  ValueDisplayed: 33.2  [0402L]  (hidden comment: CRCW040233R2FKED)
R251  ValueDisplayed: 10.0k  [0402L]  (hidden comment: CRCW040210K0FKED)
R252  ValueDisplayed: 2.49k  [0402L]  (hidden comment: CRCW04022K49FKED)
R253  ValueDisplayed: 2.49k  [0402L]  (hidden comment: CRCW04022K49FKED)
R254  ValueDisplayed: 2.49k  [0402L]  (hidden comment: CRCW04022K49FKED)
R255  ValueDisplayed: 2.49k  [0402L]  (hidden comment: CRCW04022K49FKED)
R256  ValueDisplayed: 2.49k  [0402L]  (hidden comment: CRCW04022K49FKED)
R257  ValueDisplayed: 2.49k  [0402L]  (hidden comment: CRCW04022K49FKED)
R258  ValueDisplayed: 2.49k  [0402L]  (hidden comment: CRCW04022K49FKED)
R350  ValueDisplayed: 10.0k  [0402L]  (hidden comment: CRCW040210K0FKED)
TP2  TESTPOINT  [TP_25MIL-SMT]  (value not drawn)  (no BOM)
TP3  TESTPOINT  [TP_25MIL-SMT]  (value not drawn)  (no BOM)
U4  DP83TG720SWRNDRQ1  [RND0036A]
Y5  ABM8AIG-25.000MHZ-12-2Z-T3  [Abracon_ABM8AIG]  (value not drawn)
Y6  CDC6CE02500CDLE  [DLE0004A-MFG]

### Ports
AR_SYNCIN, ETH2_EN, ETH2_INT, ETH2_NRST, ETH_TRD_N, ETH_TRD_P, MCU_CLKOUT, MSS_MDIO_CLK, MSS_MDIO_DATA, MSS_RGMII_RCLK, MSS_RGMII_RCTL, MSS_RGMII_RD0, MSS_RGMII_RD1, MSS_RGMII_RD2, MSS_RGMII_RD3, MSS_RGMII_TCLK, MSS_RGMII_TCTL, MSS_RGMII_TD0, MSS_RGMII_TD1, MSS_RGMII_TD2, MSS_RGMII_TD3, OSC_CLK_OUT_25, OSC_CLKTOP, PMIC_EN (out)

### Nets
3V3_VIO: FB1.1 FB3.1 R75.2 R79.1 R177.1
GND: C8.1 C11.1 C12.1 C13.1 C16.2 C20.2 C24.1 C32.1 C35.1 C36.1 C37.2 C40.2 C44.2 C46.1 C52.2 C54.1 C95.2 C121.2 C172.1 D10.1(CATHODE) D14.1(CATHODE) R76.1 R185.2 R251.2 R350.2 U4.37(GND) Y5.2(GND) Y6.2(GND)
PMIC_LDO_1V0: R89.2
PMICOUT_1V0: R176.2
PMICOUT_1V2: R88.2
REGOUT_3V3: R11.1 R50.2
VDD_1P0: C8.2 C11.2 C12.2 C13.2 C16.1 C20.1 FB2.2 R63.1 U4.21(VDD1P0)
VDDIO_ETH2: C32.2 C35.2 C36.2 C37.1 C44.1 C46.2 FB1.2 R13.2 R15.2 R16.2 R34.1 R46.1 R252.2 R253.2 R254.2 R255.2 R256.2 R257.2 R258.2 U4.22(VDDIO) U4.34(VDDIO)
AR_SYNCIN: R61.2 R78.2 ; port AR_SYNCIN
BAW_NC: C121.1 R168.2 R177.2 R185.1 R241.2 R242.2 R248.1 Y5.1 Y6.1(OE)
ETH2_CLKOUT: R254.1 TP2.1 U4.16(CLKOUT/GPIO_2)
ETH2_EN: C40.1 R11.2 U4.7(EN) ; port ETH2_EN
ETH2_INH: R12.2 R251.1 TP3.1 U4.10(INH)
ETH2_INT: R34.2 U4.2(~{INT}) ; port ETH2_INT
ETH2_NRST: R46.2 U4.3(~{RESET}) ; port ETH2_NRST
ETH2_RX_CLK: R15.1 R234.2 U4.27(RX_CLK)
ETH2_RX_CTRL: R245.2 R252.1 U4.15(RX_CTRL)
ETH2_XI: R186.1 R242.1 U4.5(XI)
ETH2_XO: R246.2 U4.4(XO)
ETH_TRD_N: U4.13(TRD_M) ; port ETH_TRD_N
ETH_TRD_P: U4.12(TRD_P) ; port ETH_TRD_P
LED_0: R61.1 R77.2 R258.1 U4.35(LED_0/GPIO_0)
LED_1: R13.1 R93.2 U4.6(LED_1/GPIO_1)
MCU_CLKOUT: R6.1 ; port MCU_CLKOUT
MSS_MDIO_CLK: R249.1 ; port MSS_MDIO_CLK
MSS_MDIO_DATA: R247.1 ; port MSS_MDIO_DATA
MSS_RGMII_RCLK: R234.1 ; port MSS_RGMII_RCLK
MSS_RGMII_RCTL: R245.1 ; port MSS_RGMII_RCTL
MSS_RGMII_RD0: R237.1 ; port MSS_RGMII_RD0
MSS_RGMII_RD1: R238.1 ; port MSS_RGMII_RD1
MSS_RGMII_RD2: R239.1 ; port MSS_RGMII_RD2
MSS_RGMII_RD3: R240.1 ; port MSS_RGMII_RD3
MSS_RGMII_TCLK: R74.1 ; port MSS_RGMII_TCLK
MSS_RGMII_TCTL: R230.1 ; port MSS_RGMII_TCTL
MSS_RGMII_TD0: R96.1 ; port MSS_RGMII_TD0
MSS_RGMII_TD1: R100.1 ; port MSS_RGMII_TD1
MSS_RGMII_TD2: R178.1 ; port MSS_RGMII_TD2
MSS_RGMII_TD3: R225.1 ; port MSS_RGMII_TD3
OSC_CLK_OUT_25: R241.1 ; port OSC_CLK_OUT_25
OSC_CLKTOP: R168.1 ; port OSC_CLKTOP
PMIC_EN: R12.1 ; port PMIC_EN
RX_D0: R237.2 R255.1 U4.26(RX_D0)
RX_D1: R238.2 R256.1 U4.25(RX_D1)
RX_D2: R239.2 R257.1 U4.24(RX_D2/RX_P)
RX_D3: R16.1 R240.2 U4.23(RX_D3/RX_M)
STRP_1: R78.1 R253.1 U4.14(STRP_1)
V_GND: C172.2 R76.2 R79.2 Y5.4(GND) Y6.4(VDD)
XO_combined: C95.1 R186.2 R246.1 R248.2 Y5.3 Y6.3(CLK)
NetC24_2: C24.2 C52.1 C54.2 FB3.2 U4.11(VDDA3P3)
NetD10_2: D10.2(ANODE) R77.1
NetD14_2: D14.2(ANODE) R93.1
NetFB2_1: FB2.1 R88.1 R89.1 R176.1
NetR6_2: R6.2 U4.18(STRP_DFT)
NetR50_1: R50.1 R350.1 U4.8(WAKE)
NetR63_2: R63.2 U4.9(VDD1P0)
NetR74_2: R74.2 U4.28(TX_CLK)
NetR75_1: R75.1 U4.19(ATP1)
NetR96_2: R96.2 U4.33(TX_D0/TX_M)
NetR100_2: R100.2 U4.32(TX_D1/TX_P)
NetR178_2: R178.2 U4.31(TX_D2)
NetR225_2: R225.2 U4.30(TX_D3)
NetR230_2: R230.2 U4.29(TX_CTRL)
NetR247_2: R247.2 U4.36(MDIO)
NetR249_2: R249.2 U4.1(MDC)

Not connected (* = marked no-connect by the designer): U4 17(ATP2)* 20(ATP0)*

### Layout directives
differential pair: ETH_TRD_N, ETH_TRD_P
net class RGMII: (no net found under the mark)

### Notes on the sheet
- ETHERNET
- ETHERNET PHY
- Place R74, R96, R100, R178, R225 and R230 close to U29
- Place R234, R237, R238, R239, R240 and R245 close to U4
- (near Y5) 25MHz XTAL
- (near C121) NOTE: When BAW mounted, make R79,R177, R186 and C172 as mountable
  & R76,R242,R246,R248,C95 and C121 as DNP
- BOOTSTRAP CONFIGURATION PINS
- Resistor Values must be changed to change Modes, refer to datasheet for proper values
- BAW Oscillator
- MAC [2]
- MAC [1]
- MAC [0]
- ADD2, ADD0
- ADD3, ADD1
- MAC[2:0] - 1 1 1       RGMII (RX Shift Mode)
- MAC Interface Selection Bootstraps

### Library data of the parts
C8 C11 C24 C32 C35 = CMP-0007134-5: CAP, CERM, 2.2 uF, 6.3 V, +/- 10%, X7R, AEC-Q200 Grade 1, 0603; Manufacturer: MuRata; TaMin_C: -55°C; Polarized: N; SizeAreaWB_mm2: 4.68; Value1: Unknown; U/M: EA; Value: 2.2uF; TaMax_C: 125°C; SizeZ_mm: 1; SizeX_mm: 1.6; SizeY_mm: 0.8; Cap_Case: 0603; Value2: 6.3V; SizeArea_mm2: 1.28; AEC Qualified: Y; Cap_F: 2.2µF; AEC Category: Q200
C12 C13 C36 C46 C54 C172 = CMP-0006351-2: CAP, CERM, 0.1 uF, 16 V, +/- 10%, X7R, 0402; Manufacturer: MuRata; TaMin_C: -55°C; Polarized: N; SizeAreaWB_mm2: 3; Value1: Unknown; U/M: EA; Value: 0.1uF; TaMax_C: 125°C; SizeZ_mm: 0.6; SizeX_mm: 1; SizeY_mm: 0.5; Cap_Case: 0402; Value2: 16V; CompType: Capacitor; Cap_F: 100nF; AEC Category: Q200
C16 C20 C37 C44 C52 = CMP-0006324-2: CAP, CERM, 0.01 uF, 50 V, +/- 10%, X7R, AEC-Q200 Grade 1, 0402; Manufacturer: TDK; TaMin_C: -55°C; ESR_ohm: 0.333065; Polarized: N; SizeAreaWB_mm2: 3; Value1: 0.333065 ohm; U/M: EA; Value: 0.01uF; TaMax_C: 125°C; SizeZ_mm: 0.6; SizeX_mm: 1; SizeY_mm: 0.5; Cap_Case: 0402; Value2: 50V; CompType: Capacitor; AEC Qualified: Y; Cap_F: 10nF; IRMS_A: 323.373mA; AEC Category: Q200
C40 = CMP-0006669-2: CAP, CERM, 0.047 uF, 25 V, +/- 10%, X7R, 0402; Manufacturer: MuRata; TaMin_C: -55°C; Polarized: N; SizeAreaWB_mm2: 3; Value1: Unknown; U/M: EA; TaMax_C: 125°C; SizeZ_mm: 0.6; SizeX_mm: 1; SizeY_mm: 0.5; Value2: 25V; Cap_F: 47nF; AEC Category: Q200
C95 C121 = CMP-0007071-4: CAP, CERM, 22 pF, 50 V, +/- 5%, C0G/NP0, AEC-Q200 Grade 1, 0603; Manufacturer: TDK; TaMin_C: -55°C; Polarized: N; SizeAreaWB_mm2: 4.68; Value1: Unknown; U/M: EA; Value: 22pF; TaMax_C: 125°C; SizeZ_mm: 1; SizeX_mm: 1.6; SizeY_mm: 0.8; Value2: 50V; SizeArea_mm2: 1.28; CompType: Capacitor; AEC Qualified: Y; AEC Category: Q200
D10 = CMP-0120222-1: Yellow 590nm LED Indication - Discrete 2.1V 0402 (1006 Metric); Manufacturer: Rohm Semiconductor; Power_TotalModule: 52mW; SizeZ_mm: 0.25mm; Tjmax_C: 110°C; Vr_V: 5V; AEC Qualified: No; Forward Current: 20mA; Led Orientation: Top View; Luminous Intensity: 100mcd
D14 = CMP-0120221-1: LED Uni-Color Orange 2-Pin Chip 0402(1006Metric) T/R; Manufacturer: Rohm Semiconductor; LambdaD: 605nm; Power_TotalModule: 52mW; SizeZ_mm: 0.25mm; Tjmax_C: 110°C; Vf_V: 2.1V; Vr_V: 5V; AEC Qualified: No; Forward Current: 20mA; Led Orientation: Top View; Luminous Intensity: 100mcd
FB1 = CMP-0003348-2: Ferrite Bead, 1000 ohm @ 100 MHz, 0.6 A, 0603; Manufacturer: MuRata; Ztyp@1GHz_Ohm: 1k; SizeAreaWB_mm2: 4.68; DCR_ohm: 3.5d; Value1: 0.35 ohm; Imax_A: 6dA; SizeZ_mm: 1; SizeX_mm: 1.6; SizeY_mm: 0.8; Value2: 0.6A; SizeArea_mm2: 1.28
FB2 FB3 = CMP-0089848-1: 600 Ohms @ 100MHz 1 Power Line Ferrite Bead 0603 (1608 Metric) 1.3A 150mOhm; Manufacturer: Murata; Tolerance_%: 25%; SizeZ_mm: 0.95mm; Impedance At Frequency: 600Ω @ 100MHz; AEC Qualified: Yes; AEC Grade: Grade 1; DCR_ohm: 0.15
R6 R50 R76 R79 R168 R186 R241 R246 = CMP-0026992-3: RES, 0, 5%, 0.1 W, AEC-Q200 Grade 0, 0402; Manufacturer: Panasonic; Power_W: 100mW; TempCo: 600 ppm/C; Value_Code: 0000; Value: 0; EIA_Code: E24; SizeX_mm: 1; SizeY_mm: 0.5; SizeZ_mm: 0.6; Value2: 0.1W; AEC Qualified: Y; VDC_V: 50V; AEC Category: Q200; SizeAreaWB_mm2: 3
R11 R46 R177 R185 R251 R350 = CMP-0025958-3: RES, 10.0 k, 1%, 0.063 W, AEC-Q200 Grade 0, 0402; Manufacturer: Vishay-Dale; Power_W: 63mW; TempCo: 100 ppm/C; Value_Code: 10k0; Value: 10.0k; EIA_Code: E96; Res_ohm: 10k; SizeX_mm: 1; SizeY_mm: 0.5; SizeZ_mm: 0.6; Value2: 0.063W; CompType: Resistor; AEC Qualified: Y; VDC_V: 50V; AEC Category: Q200; AEC Grade: 0
R12 R61 R78 = CMP-0027008-4: as R344 on sheet PROC158A_Ethernet_PHY
R13 R15 R16 R75 R252-R258 = CMP-0026237-2: as R92 on sheet PROC158A_Ethernet_PHY
R34 = CMP-0026890-5: as R340 on sheet PROC158A_Ethernet_PHY
R63 = CMP-0081856-1: RES, 0, 0%, 0.2 W, AEC-Q200 Grade 0, 0402; Manufacturer: Vishay-Dale; SizeAreaWB_mm2: 3; SizeArea_mm2: 0.5; AEC Qualified: Y; AEC Category: Q200; Value: 0; SizeZ_mm: 0.6; Power_W: 200mW; VDC_V: 50V; Value2: 0.2W; SizeX_mm: 1
R74 R96 R100 R178 R225 R230 R234 R237-R240 R245 R247 R249 = CMP-0026299-2: as R98 on sheet PROC158A_Ethernet_PHY
R77 R93 = CMP-0026699-1: as R108 on sheet PROC158A_Ethernet_PHY
R88 R89 R176 = CMP-0091690-1: RES 0 OHM JUMPER 1/4W 0603; Manufacturer: Stackpole Electronics; Power_W: 250mW; AEC Grade: Grade 0; AEC Qualified: Yes; SizeZ_mm: 0.7mm; Value: 0
R242 = CMP-0026993-2: RES, 100, 5%, 0.1 W, AEC-Q200 Grade 0, 0402; Manufacturer: Panasonic; Power_W: 100mW; TempCo: 200 ppm/C; Value_Code: 100R; U/M: EA; Value: 100; EIA_Code: E24; SizeX_mm: 1; SizeY_mm: 0.5; SizeZ_mm: 0.6; Value2: 0.1W; AEC Qualified: Y; AEC Grade: 0; AEC Category: Q200
R248 = CMP-0022138-4: RES, 1.00 M, 1%, 0.1 W, AEC-Q200 Grade 0, 0603; Manufacturer: Vishay-Dale; Power_W: 100mW; TempCo: 100 ppm/C; Value_Code: 1M00; Value: 1.00Meg; EIA_Code: E96; Res_ohm: 1M; SizeX_mm: 1.6; SizeY_mm: 0.8; SizeZ_mm: 1; Value2: 0.1W; SizeArea_mm2: 1.28; AEC Qualified: Y; VDC_V: 75V; AEC Category: Q200; AEC Grade: 0
TP2 TP3 = CMP-0078143-3: TEST POINT.  No entry in BOM.
U4 = CMP-0085268-1: Low Power Auto PHY 1000BASE-T1 Automotive Ethernet Physical Layer Transceiver, RND0036A (VQFNP-36); Alternate Manufacturer: Texas Instruments; Alternate PartNumber: DP83TG720SWRNDTQ1; SizeY_mm: 6; SizeAreaWB_mm2: 64; SizeZ_mm: 0.9; AEC Qualified: Y; SizeArea_mm2: 36; AEC Category: Q200; CompType: IC
Y5 = CMP-0004682-5: Crystal, 25 MHz, 12pF, AEC-Q200 Grade 1, SMD; Manufacturer: Abracon Corporation; TaMin_C: -40°C; Frequency Stability: 50 ppm; SizeAreaWB_mm2: 14.7; Frequency_Fixed: 25MHz; TaMax_C: 125°C; SizeZ_mm: 0.8; SizeX_mm: 2.5; SizeY_mm: 3.2; SizeArea_mm2: 8; AEC Category: Q200; AEC Grade: 1; AEC Qualified: Y
Y6 = CMP-0001498-1: Low Jitter, Low Power, LVCMOS Output, BAW Oscillator; Manufacturer: Texas Instruments; SizeZ_mm: 1mm; AEC Qualified: Yes; AEC Grade: Grade 1; Frequency Stability: 20ppm; Frequency_Fixed: 25MHz; Max Supply Current: 5mA; Max Supply Voltage: 3.63V; Min Supply Voltage: 1.62V; Standoff Height: 0mm

## Sheet PROC158A_Auto_Ethernet_conn.SchDoc
size 431 x 279 mm; Date: Not shown in title block; ApprovedBy: Not shown in title block; CheckedBy: Not shown in title block; Author: Not shown in title block; CompanyName: Not shown in title block; Engineer: Not shown in title block; Organization: Not shown in title block; Address1: Not shown in title block; Address2: Not shown in title block; Address3: Not shown in title block; Address4: Not shown in title block; DocumentNumber: 15; Revision: Use project parameter SCH_Rev; SheetNumber: 15; SheetTotal: 24; PageSetup: Record=PageOptions¦CenterHorizontal=True¦CenterVertical=True¦PrintScale=1.00¦XCorrection=1.00¦YCorrection=1.00¦PrintKind=0¦BorderSize=5000000¦LeftOffset=0¦BottomOffset=0¦Orientation=2¦PaperLength=1000¦PaperWidth=1000¦Scale=100¦PaperSource=15¦PrintQuality=600¦MediaType=1¦DitherType=10¦PaperKind=Letter¦PrintScaleMode=1
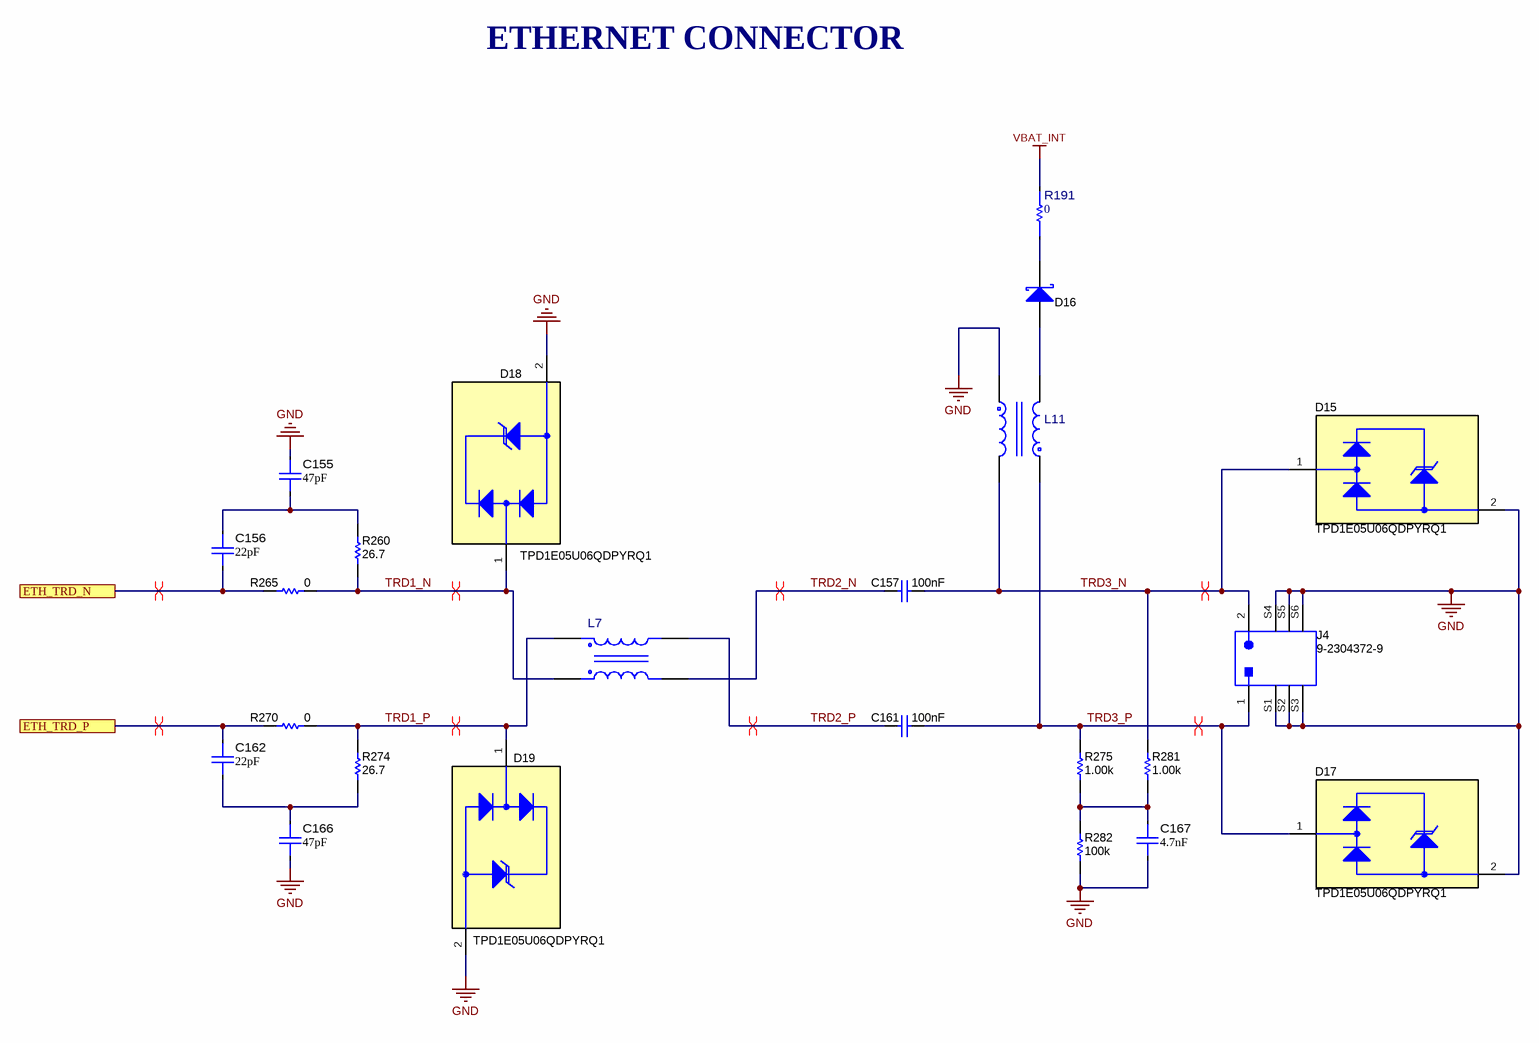
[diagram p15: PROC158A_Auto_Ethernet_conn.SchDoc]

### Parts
C155  ValueDisplayed: 47pF  [FP-KGM05ACG1H470FH_0402-MFG]  (hidden comment: KGM05ACG1H470FH)
C156  ValueDisplayed: 22pF  [FP-KGM05ACG1H220FH_0402-MFG]  (hidden comment: KGM05ACG1H220FH)
C157  Cap_F: 100nF  [0805_HV]  (hidden comment: CGA4J2X7R2A104K125AA)
C161  Cap_F: 100nF  [0805_HV]  (hidden comment: CGA4J2X7R2A104K125AA)
C162  ValueDisplayed: 22pF  [FP-KGM05ACG1H220FH_0402-MFG]  (hidden comment: KGM05ACG1H220FH)
C166  ValueDisplayed: 47pF  [FP-KGM05ACG1H470FH_0402-MFG]  (hidden comment: KGM05ACG1H470FH)
C167  ValueDisplayed: 4.7nF  [FP-CC1206KKX7RCBB472_1206-MFG]  (hidden comment: CC1206KKX7RCBB472)
D15  TPD1E05U06QDPYRQ1  [DPY0002A]
D16  PMEG6020ER,115  [SOD-123W]  (value not drawn)
D17  TPD1E05U06QDPYRQ1  [DPY0002A]
D18  TPD1E05U06QDPYRQ1  [DPY0002A]
D19  TPD1E05U06QDPYRQ1  [DPY0002A]
J4  9-2304372-9  [TE_9-2304372-9]
L7  DLW32MH101XT2  [FP-DLW32MH101XT2_1210-MFG]  (value not drawn)
L11  ADL32VHR-3R9M  [FP-ADL32VHR-3R9M_SMT_3MM2_2MM5-MFG]  (value not drawn)
R191  value 0  [FP-HCJ0805ZT0R00_0805-MFG]  (hidden comment: HCJ0805ZT0R00)
R260  ValueDisplayed: 26.7  [0402L]  (hidden comment: CRCW040226R7FKED)
R265  ValueDisplayed: 0  [0402L]  (hidden comment: CRCW04020000Z0EDHP)
R270  ValueDisplayed: 0  [0402L]  (hidden comment: CRCW04020000Z0EDHP)
R274  ValueDisplayed: 26.7  [0402L]  (hidden comment: CRCW040226R7FKED)
R275  ValueDisplayed: 1.00k  [0805L]  (hidden comment: ERJ-P06F1001V)
R281  ValueDisplayed: 1.00k  [0805L]  (hidden comment: ERJ-P06F1001V)
R282  ValueDisplayed: 100k  [0805_HV]  (hidden comment: CRCW0805100KJNEA)

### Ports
ETH_TRD_N, ETH_TRD_P

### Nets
GND: C155.1 C166.2 C167.2 D15.2(GND) D17.2(GND) D18.2(GND) D19.2(GND) J4.S1(GND) J4.S2(GND) J4.S3(GND) J4.S4(GND) J4.S5(GND) J4.S6(GND) L11.3 R282.1
VBAT_INT: R191.2
ETH_TRD_N: C156.2 R265.1 ; port ETH_TRD_N
ETH_TRD_P: C162.1 R270.1 ; port ETH_TRD_P
TRD1_N: D18.1(I/O) L7.4 R260.1 R265.2
TRD1_P: D19.1(I/O) L7.1 R270.2 R274.2
TRD2_N: C157.2 L7.3
TRD2_P: C161.2 L7.2
TRD3_N: C157.1 D15.1(I/O) J4.2 L11.4 R281.2
TRD3_P: C161.1 D17.1(I/O) J4.1 L11.1 R275.2
NetC155_2: C155.2 C156.1 R260.2
NetC162_2: C162.2 C166.1 R274.1
NetC167_1: C167.1 R275.1 R281.1 R282.2
NetD16_1: D16.1(K) R191.1
NetD16_2: D16.2(A) L11.2

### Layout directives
differential pair: ETH_TRD_N, ETH_TRD_P, TRD1_N, TRD1_P, TRD2_N, TRD2_P, TRD3_N, TRD3_P

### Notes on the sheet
- ETHERNET CONNECTOR

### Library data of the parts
C155 C166 = CMP-0120220-1: 47 pF ±1% 50V Ceramic Capacitor C0G, NP0 0402 (1005 Metric); Manufacturer: KYOCERA AVX; AEC Qualified: No; SizeZ_mm: 0.56mm; TempCo: 30ppm/°C; Value: 47pF
C156 C162 = CMP-0120219-1: 22 pF ±1% 50V Ceramic Capacitor C0G, NP0 0402 (1005 Metric); Manufacturer: KYOCERA AVX; AEC Qualified: No; SizeZ_mm: 0.56mm; TempCo: 30ppm/°C; Value: 22pF
C157 C161 = CMP-0007969-2: CAP, CERM, 0.1 uF, 100 V, +/- 10%, X7R, AEC-Q200 Grade 1, 0805; Manufacturer: TDK; TaMin_C: -55°C; ESR_ohm: 0.020726; Polarized: N; SizeAreaWB_mm2: 6.75; Value1: 0.020726 ohm; U/M: EA; Value: 0.1uF; TaMax_C: 125°C; SizeZ_mm: 1.45; SizeX_mm: 2; SizeY_mm: 1.25; Cap_Case: 0805; Value2: 100V; SizeArea_mm2: 2.5; AEC Qualified: Y; IRMS_A: 1.456A; AEC Grade: 1; AEC Category: Q200
C167 = CMP-0120216-1: 4700 pF ±10% 1000V (1kV) Ceramic Capacitor X7R 1206 (3216 Metric); Manufacturer: YAGEO; AEC Qualified: No; SizeZ_mm: 1.45mm; TempCo: 15%; Value: 4.7nF
D15 D17-D19 = CMP-0073591-4: Automotive 1-Channel Ultra-Low-Capacitance IEC ESD Protection Diode, DPY0002A (X1SON-2); Alternate Manufacturer: Texas Instruments; Alternate PartNumber: TPD1E05U06QDPYTQ1; SizeZ_mm: 0.45; SizeAreaWB_mm2: 3.2; SizeArea_mm2: 0.6; CompType: IC; AEC Category: Q200; AEC Qualified: Y; SizeX_mm: 1.0
D16 = CMP-0076989-2: Diode, Schottky, 60 V, 2 A, SOD-123W; Manufacturer: Nexperia; AEC Category: Q101; Vr_V: 60V; TJmax_C: 150°C; Green_Lifecycle: Not Set; Value1: 2A; SizeZ_mm: 1.0; Vf_V: 530mV; SizeY_mm: 1.7; Value2: 0.53V; Value: 60V; SizeArea_mm2: 5.95; SizeAreaWB_mm2: 12.15; Green_REACh: Incomplete; SizeX_mm: 3.5
J4 = CMP-0078655-1: 1 Port Header Assembly, TH; Manufacturer: TE Connectivity; Gender: Male; CompType: Connector; Shrouded: Y
L7 = CMP-0090833-1: 100μH @ 100kHz 2 Line Common Mode Choke Surface Mount 100mA DCR 3.12Ω; Manufacturer: Murata; AEC Qualified: Yes; SizeZ_mm: 2.5mm; DCR_ohm: 3.12; AEC Grade: Grade 1; Tolerance_%: -25/+50%
L11 = CMP-0098175-1: Differential Mode Choke 3.9uH 540mA 0.36Ohm 3.2x2.5x2.5mm SMT; Manufacturer: TDK; Ind_H: 3.9µH; Isat: 860mA; DCR_ohm: 0.36; Tolerance_%: 20%; SizeZ_mm: 2.5mm; Test Frequency: 100kHz; AEC Qualified: No
R191 = CMP-0091603-1: 0 Ohms Jumper 0.5W, 1/2W Chip Resistor 0805 (2012 Metric) Automotive AEC-Q200 Metal Foil; Manufacturer: Stackpole; SizeZ_mm: 0.85mm; Power: 500mW; AEC Grade: Grade 0; AEC Qualified: Yes
R260 = CMP-0026210-2: RES, 26.7, 1%, 0.063 W, AEC-Q200 Grade 0, 0402; Manufacturer: Vishay-Dale; Power_W: 63mW; TempCo: 100 ppm/C; Value_Code: 26R7; Value: 26.7; SizeX_mm: 1; SizeY_mm: 0.5; SizeZ_mm: 0.6; Value2: 0.063W; AEC Qualified: Y; VDC_V: 50V; AEC Grade: 0; AEC Category: Q200; EIA_Code: E96
R265 R270 = CMP-0081856-1: as R63 on sheet PROC158A_Auto_Ethernet_PHY
R274 = CMP-0026210-2: RES, 26.7, 1%, 0.063 W, AEC-Q200 Grade 0, 0402; Manufacturer: Vishay-Dale; Power_W: 63mW; TempCo: 100 ppm/C; Value_Code: 26R7; Value: 26.7; SizeX_mm: 1; SizeY_mm: 0.5; SizeZ_mm: 0.6; Value2: 0.063W; CompType: Resistor; AEC Qualified: Y; VDC_V: 50V; AEC Grade: 0; AEC Category: Q200; EIA_Code: E96
R275 R281 = CMP-0021848-2: RES, 1.00 k, 1%, 0.25 W, 0805; Manufacturer: Panasonic; Power_W: 250mW; TempCo: 100 ppm/C; Value_Code: 1k00; U/M: EA; Value: 1.00k; EIA_Code: E96; Res_ohm: 1k; SizeX_mm: 2; SizeY_mm: 1.25; SizeZ_mm: 1.45; Value2: 0.25W; SizeArea_mm2: 2.5; VDC_V: 400V; AEC Category: Q200
R282 = CMP-0020444-3: RES, 100 k, 5%, 0.125 W, AEC-Q200 Grade 0, 0805; Manufacturer: Vishay-Dale; Power_W: 125mW; TempCo: 200 ppm/C; Value: 100k; EIA_Code: E24; SizeX_mm: 2; SizeY_mm: 1.25; SizeZ_mm: 1.45; Value2: 0.125W; SizeArea_mm2: 2.5; AEC Qualified: Y; VDC_V: 150V; AEC Category: Q200; AEC Grade: 0

## Sheet PROC158A_FTDI_PWR.SchDoc
size 431 x 279 mm; Date: Not shown in title block; ApprovedBy: Not shown in title block; CheckedBy: Not shown in title block; Author: Not shown in title block; CompanyName: Not shown in title block; Engineer: Not shown in title block; Organization: Not shown in title block; Address1: Not shown in title block; Address2: Not shown in title block; Address3: Not shown in title block; Address4: Not shown in title block; DocumentNumber: 16; Revision: Use project parameter SCH_Rev; SheetNumber: 16; SheetTotal: 24; PageSetup: Record=PageOptions¦CenterHorizontal=True¦CenterVertical=True¦PrintScale=1.00¦XCorrection=1.00¦YCorrection=1.00¦PrintKind=0¦BorderSize=5000000¦LeftOffset=0¦BottomOffset=0¦Orientation=2¦PaperLength=1000¦PaperWidth=1000¦Scale=100¦PaperSource=15¦PrintQuality=600¦MediaType=1¦DitherType=10¦PaperKind=Letter¦PrintScaleMode=1
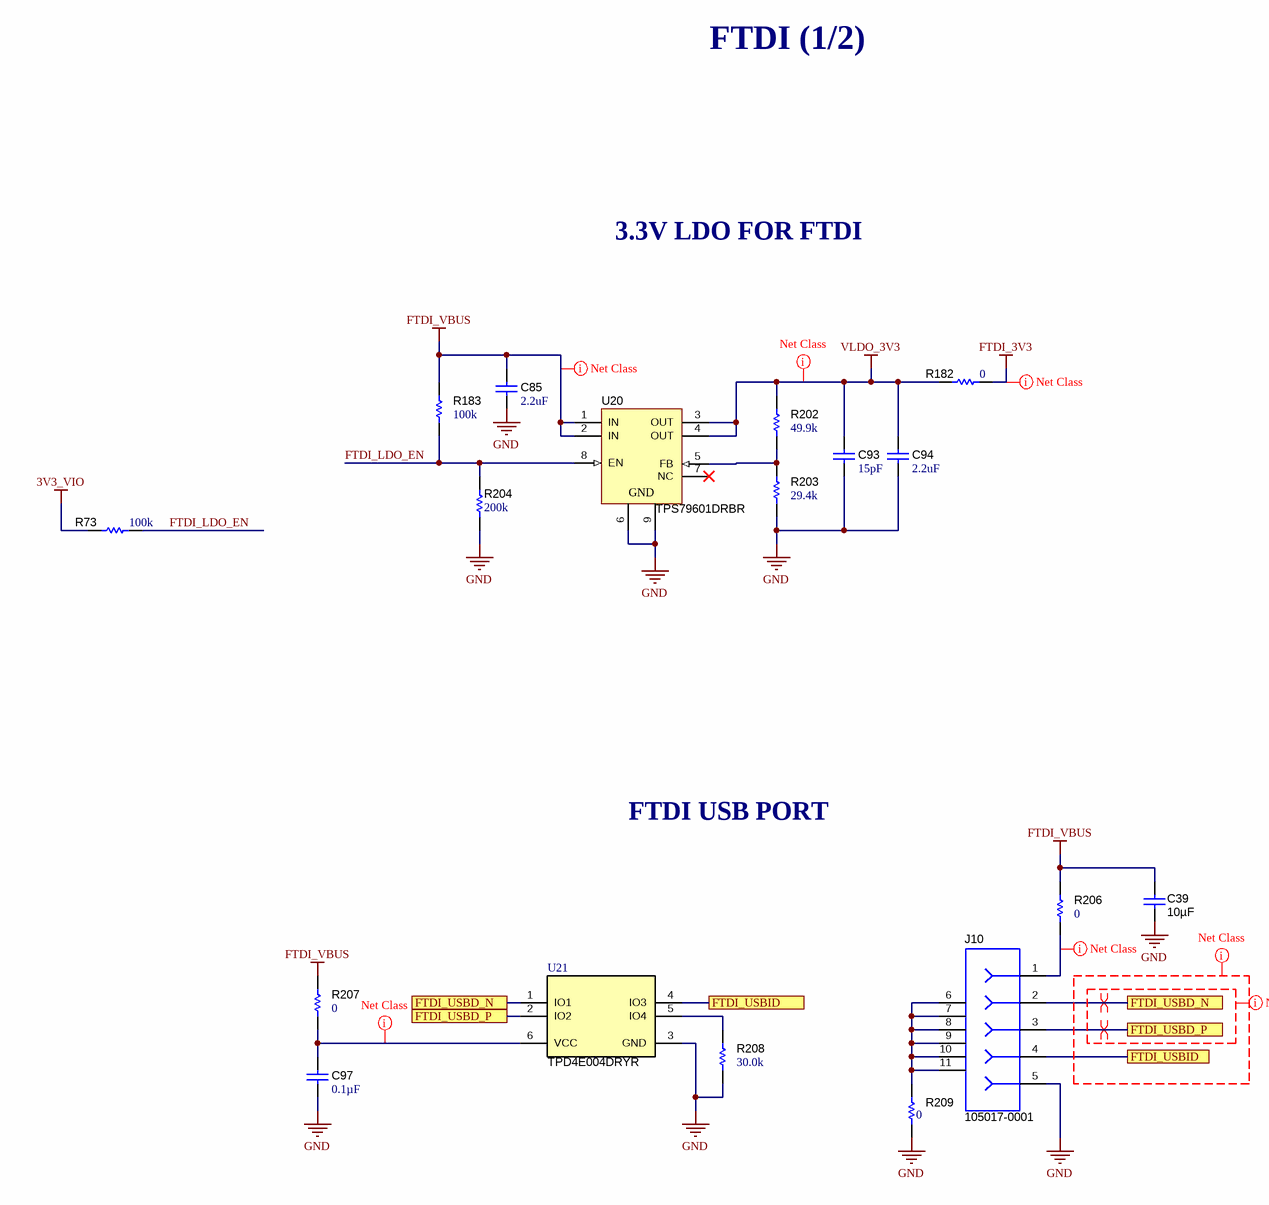
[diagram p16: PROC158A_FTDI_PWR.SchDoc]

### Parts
C39  Cap_F: 10µF  [0805L]  (hidden comment: CL21B106KOQNNNE)
C85  ValueDisplayed: 2.2uF  [0402_065L]  (hidden comment: C1005X7S1A225K050BC)
C93  ValueDisplayed: 15pF  [0402L]  (hidden comment: 04025A150FAT2A)
C94  ValueDisplayed: 2.2uF  [0402_065L]  (hidden comment: C1005X7S1A225K050BC)
C97  ValueDisplayed: 0.1µF  [0402L]  (hidden comment: C0402C104K8RACTU)
J10  105017-0001  [CONN_105017-0001]
R73  ValueDisplayed: 100k  [0402L]  (hidden comment: CRCW0402100KFKED)
R182  ValueDisplayed: 0  [0805L]  (hidden comment: CRCW08050000Z0EA)
R183  ValueDisplayed: 100k  [0402L]  (hidden comment: CRCW0402100KFKED)
R202  ValueDisplayed: 49.9k  [0402L]  (hidden comment: CRCW040249K9FKED)
R203  ValueDisplayed: 29.4k  [0402L]  (hidden comment: CRCW040229K4FKED)
R204  ValueDisplayed: 200k  [0402L]  (hidden comment: CRCW0402200KFKED)
R206  ValueDisplayed: 0  [0805L]  (hidden comment: CRCW08050000Z0EA)
R207  ValueDisplayed: 0  [0805L]  (hidden comment: CRCW08050000Z0EA)
R208  ValueDisplayed: 30.0k  [0402L]  (hidden comment: CRCW040230K0FKED)
R209  ValueDisplayed: 0  [0402L]  (hidden comment: ERJ-2GE0R00X)
U20  TPS79601DRBR  [DRB0008B]
U21  TPD4E004DRYR  [DRY0006A]

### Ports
FTDI_USBD_N, FTDI_USBD_P, FTDI_USBID

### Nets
3V3_VIO: R73.2
FTDI_3V3: R182.2
FTDI_VBUS: C39.1 C85.1 R183.2 R206.2 R207.2 U20.1(IN) U20.2(IN)
GND: C39.2 C85.2 C93.2 C94.2 C97.2 J10.5 R203.2 R204.1 R208.1 R209.1 U20.6(GND) U20.9(GND) U21.3(GND)
VLDO_3V3: C93.1 C94.1 R182.1 R202.2 U20.3(OUT) U20.4(OUT)
FTDI_LDO_EN: R73.1 R183.1 R204.2 U20.8(EN)
FTDI_USBD_N: J10.2 U21.1(IO1) ; port FTDI_USBD_N
FTDI_USBD_P: J10.3 U21.2(IO2) ; port FTDI_USBD_P
FTDI_USBID: J10.4 U21.4(IO3) ; port FTDI_USBID
NetC97_1: C97.1 R207.1 U21.6(VCC)
NetJ10_1: J10.1 R206.1
NetJ10_6: J10.6 J10.7 J10.8 J10.9 J10.10 J10.11 R209.2
NetR202_1: R202.1 R203.1 U20.5(FB)
NetR208_2: R208.2 U21.5(IO4)

Not connected (* = marked no-connect by the designer): U20 7(NC)*

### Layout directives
net class FTDI_USB: (no net found under the mark)
net class PWR: FTDI_3V3, FTDI_VBUS, NetC97_1, NetJ10_1, VLDO_3V3
differential pair: FTDI_USBD_N, FTDI_USBD_P
net class USB_DIFF: (no net found under the mark)

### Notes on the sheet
- FTDI (1/2)
- 3.3V LDO FOR FTDI
- FTDI USB PORT

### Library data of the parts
C39 = CMP-0007995-2: CAP, CERM, 10 uF, 16 V, +/- 10%, X7R, 0805; Manufacturer: Samsung Electro-Mechanics; TaMin_C: -55°C; Polarized: N; SizeAreaWB_mm2: 6.75; Value1: Unknown; U/M: EA; Value: 10uF; TaMax_C: 125°C; SizeZ_mm: 1.45; SizeX_mm: 2; SizeY_mm: 1.25; Cap_Case: 0805; Value2: 16V; SizeArea_mm2: 2.5; AEC Category: Q200
C85 C94 = CMP-0006302-2: CAP, CERM, 2.2 uF, 10 V, +/- 10%, X7S, 0402; Manufacturer: TDK; TaMin_C: -55°C; ESR_ohm: 5.925m; Polarized: N; SizeAreaWB_mm2: 3; Value1: 0.005925 ohm; U/M: EA; Value: 2.2uF; TaMax_C: 125°C; SizeZ_mm: 0.65; SizeX_mm: 1; SizeY_mm: 0.5; Cap_Case: 0402_065; Value2: 10V; CompType: Capacitor; Cap_F: 2.2µF; IRMS_A: 2.05591A; AEC Category: Q200
C93 = CMP-0078217-1: CAP, CERM, 15 pF, 50 V,+/- 1%, C0G/NP0, 0402; Manufacturer: AVX; TaMin_C: -55°C; Polarized: N; Green_Lifecycle: Not Set; SizeAreaWB_mm2: 3; Green_REACh: Incomplete; U/M: EA; Value: 15pF; TaMax_C: 125°C; SizeZ_mm: 0.6; SizeX_mm: 1; SizeY_mm: 0.5; Cap_Case: 0402; Value2: 50V; AEC Category: Q200
C97 = CMP-0078241-1: CAP, CERM, 0.1 µF, 10 V,+/- 10%, X7R, 0402; Manufacturer: Kemet; TaMin_C: -55°C; Polarized: N; SizeAreaWB_mm2: 3; U/M: EA; Value: 0.1uF; TaMax_C: 125°C; SizeZ_mm: 0.6; SizeX_mm: 1; SizeY_mm: 0.5; Cap_Case: 0402; Value2: 10V; Cap_F: 100nF; AEC Category: Q200
J10 = CMP-0055293-1: Connector, Receptacle, Micro-USB Type B, R/A, Bottom Mount SMT; Manufacturer: Molex; CNHeader: FALSE; Green_Lifecycle: Active; Gender: Female; Green_REACh: Passed; CompType: USB; CT: TRUE
R73 R183 = CMP-0025950-3: RES, 100 k, 1%, 0.063 W, AEC-Q200 Grade 0, 0402; Manufacturer: Vishay-Dale; Power_W: 63mW; TempCo: 100 ppm/C; Value: 100k; EIA_Code: E96; SizeX_mm: 1; SizeY_mm: 0.5; SizeZ_mm: 0.6; Value2: 0.063W; CompType: Resistor; AEC Qualified: Y; VDC_V: 50V; AEC Category: Q200; AEC Grade: 0; INSTALLATION: DNP
R182 R206 R207 = CMP-0020442-3: RES, 0, 5%, 0.125 W, AEC-Q200 Grade 0, 0805; Manufacturer: Vishay-Dale; Power_W: 125mW; TempCo: 200 ppm/C; Value_Code: 0000; Value: 0; EIA_Code: E24; SizeX_mm: 2; SizeY_mm: 1.25; SizeZ_mm: 1.45; Value2: 0.125W; SizeArea_mm2: 2.5; AEC Qualified: Y; VDC_V: 150V; AEC Category: Q200
R202 = CMP-0026403-2: RES, 49.9 k, 1%, 0.063 W, AEC-Q200 Grade 0, 0402; Manufacturer: Vishay-Dale; Power_W: 63mW; TempCo: 100 ppm/C; Value_Code: 49k9; Value: 49.9k; EIA_Code: E96; SizeX_mm: 1; SizeY_mm: 0.5; SizeZ_mm: 0.6; Value2: 0.063W; AEC Qualified: Y; VDC_V: 50V; AEC Category: Q200; AEC Grade: 0
R203 = CMP-0026225-2: RES, 29.4 k, 1%, 0.063 W, AEC-Q200 Grade 0, 0402; Manufacturer: Vishay-Dale; Power_W: 63mW; TempCo: 100 ppm/C; Value_Code: 29k4; Value: 29.4k; EIA_Code: E96; SizeX_mm: 1; SizeY_mm: 0.5; SizeZ_mm: 0.6; Value2: 0.063W; AEC Qualified: Y; VDC_V: 50V; AEC Category: Q200; AEC Grade: 0
R204 = CMP-0026158-2: RES, 200 k, 1%, 0.063 W, AEC-Q200 Grade 0, 0402; Manufacturer: Vishay-Dale; Power_W: 63mW; TempCo: 100 ppm/C; Value: 200k; EIA_Code: E96; SizeX_mm: 1; SizeY_mm: 0.5; SizeZ_mm: 0.6; Value2: 0.063W; AEC Qualified: Y; VDC_V: 50V; AEC Category: Q200; AEC Grade: 0
R208 = CMP-0078244-2: RES, 30.0 k, 1%, 0.063 W, AEC-Q200 Grade 0, 0402; Manufacturer: Vishay-Dale; Power_W: 63mW; Green_Lifecycle: Active; TempCo: 100 ppm/C; Value_Code: 30k0; Green_REACh: Passed; Value: 30.0k; Res_ohm: 30k; SizeX_mm: 1; SizeY_mm: 0.5; SizeZ_mm: 0.6; Value2: 0.063W; AEC Qualified: Y; VDC_V: 50V; AEC Grade: 0; AEC Category: Q200
R209 = CMP-0026992-3: as R6 on sheet PROC158A_Auto_Ethernet_PHY
U20 = CMP-0036402-3: Single Output High PSRR LDO, 1 A, Adjustable 1.2 to 5.5 V Output, 2.7 to 5.5 V Input, 8-pin SON (DRB), -40 to 125 degC, Green (RoHS & no Sb/Br); Manufacturer: Texas Instruments; Vin(Min)(V): 2.7; Vout Adj(Max)(V): 5.5; Vout Adj(Min)(V): 1.2; Accuracy(%): 2; SubFamily: Single Channel LDO; Iq(Typ)(mA): 0.26; Vdo(Typ)(mV): 250; Iout(Max)(A): 1; AEC Category: Q200; AEC Qualified: N; CompType: IC; SizeAreaWB_mm2: 16.0; SizeArea_mm2: 9.0; SizeX_mm: 3.0; SizeZ_mm: 1.0
U21 = CMP-0043115-3: 4-Channel ESD Protection Array for High-Speed Data Interfaces, DRY0006A (USON-6); Manufacturer: Texas Instruments; IO Leakage Current(nA): 1; USB High Speed: TRUE; IO Capacitance(Typ)(pF): 1.6; Eco-Plan: Green (RoHS & no Sb/Br); IEC 61000-4-2 Contact(+/- kV): 8; Breakdown Voltage(Min)(V): 6; IEC 61000-4-2 Air-Gap(+/- kV): 12; AEC Category: Q200; AEC Qualified: N; CompType: IC; SizeAreaWB_mm2: 4.9; SizeArea_mm2: 1.45; SizeX_mm: 1.0; SizeZ_mm: 0.6; Rating: Catalog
